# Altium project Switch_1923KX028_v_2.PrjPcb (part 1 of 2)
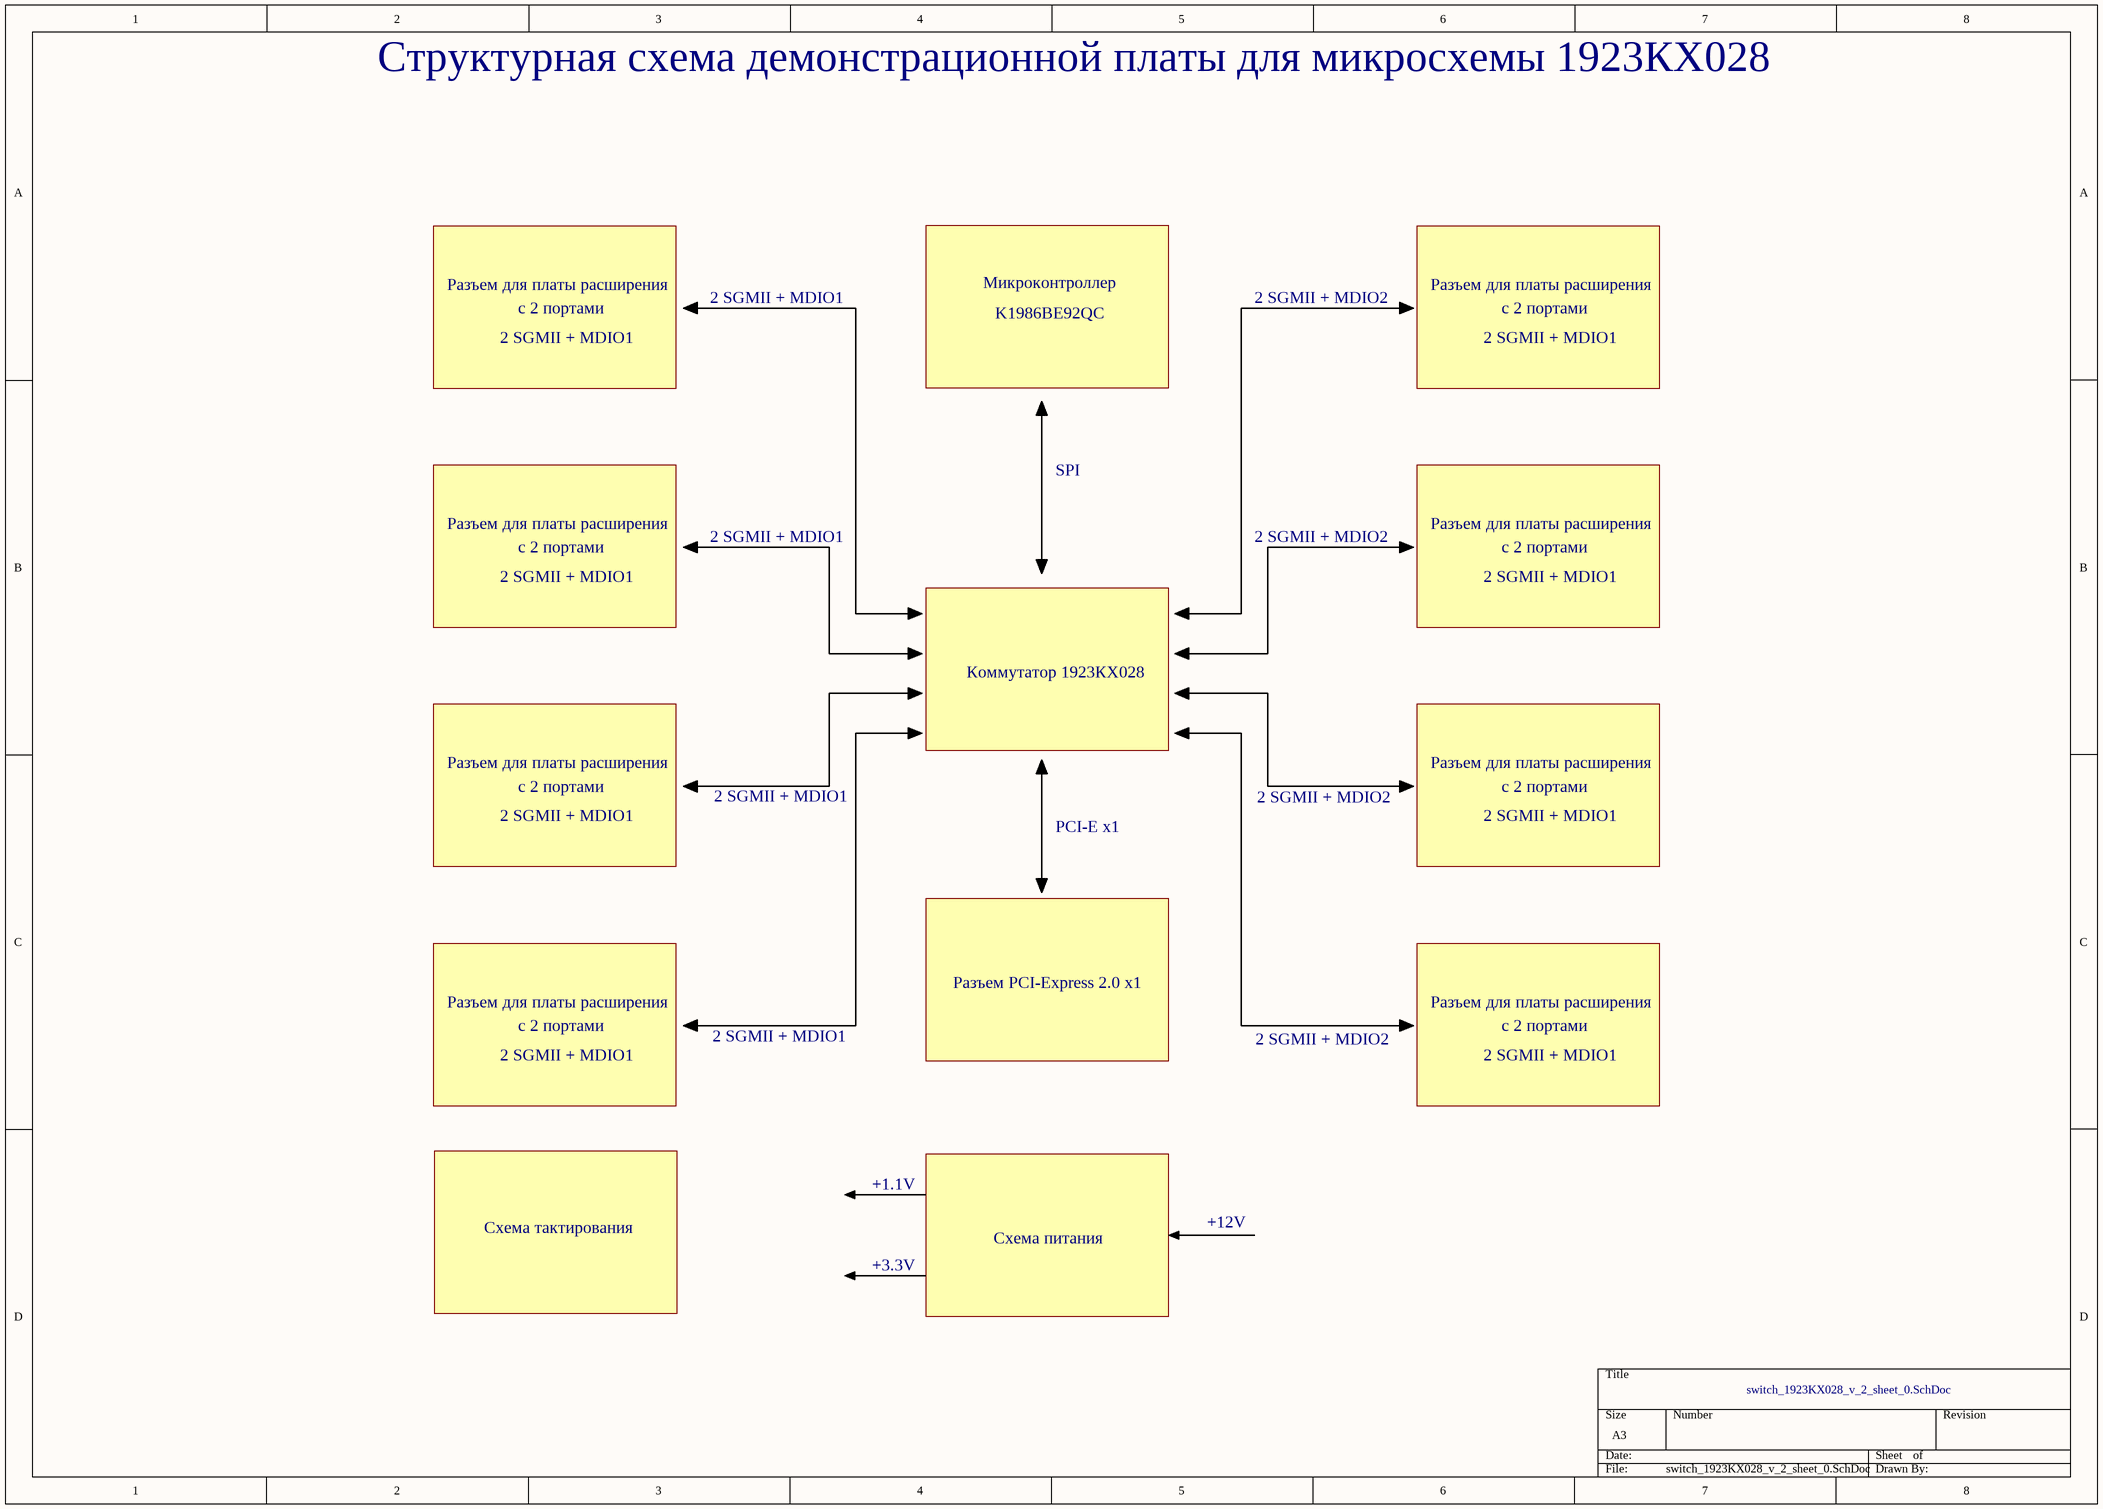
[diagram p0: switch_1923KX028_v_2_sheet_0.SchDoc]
9 sheets, 545 parts. Net scope: global (net labels, ports and power ports of the same name join across sheets).
Board file: pcb_switch_1923KX028_v_2.PcbDoc
Sheets:
  switch_1923KX028_v_2_sheet_0.SchDoc
  switch_1923KX028_v_2_sheet_1.SchDoc
  switch_1923KX028_v_2_sheet_2.SchDoc
  switch_1923KX028_v_2_sheet_3.SchDoc
  switch_1923KX028_v_2_sheet_4.SchDoc
  switch_1923KX028_v_2_sheet_5.SchDoc
  switch_1923KX028_v_2_sheet_6.SchDoc
  switch_1923KX028_v_2_sheet_7.SchDoc
  switch_1923KX028_v_2_sheet_8.SchDoc

## Sheet switch_1923KX028_v_2_sheet_0.SchDoc
size A3; DocumentNumber: 1; SheetNumber: 1; SheetTotal: 10; PageSetup: Record=PageOptions¦CenterHorizontal=True¦CenterVertical=True¦PrintScale=1.04¦XCorrection=1.00¦YCorrection=1.00¦PrintKind=1¦BorderSize=5000000¦LeftOffset=0¦BottomOffset=0¦Orientation=2¦PaperLength=1000¦PaperWidth=1000¦Scale=100¦PaperSource=7¦PrintQuality=-3¦MediaType=1¦DitherType=10¦PrintScaleMode=1¦PaperKind=A3¦PaperIndex=8

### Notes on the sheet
- Структурная схема демонстрационной платы для микросхемы 1923КХ028
- Разъем для платы расширения
- с 2 портами
- 2 SGMII + MDIO1
- Микроконтроллер
- 2 SGMII + MDIO2
- K1986ВЕ92QC
- SPI
- Коммутатор 1923КХ028
- PCI-E x1
- Разъем PCI-Express 2.0 x1
- +1.1V
- Схема тактирования
- Схема питания
- +12V
- +3.3V

## Sheet switch_1923KX028_v_2_sheet_1.SchDoc
size A3; DocumentNumber: 2; SheetNumber: 2; SheetTotal: 10
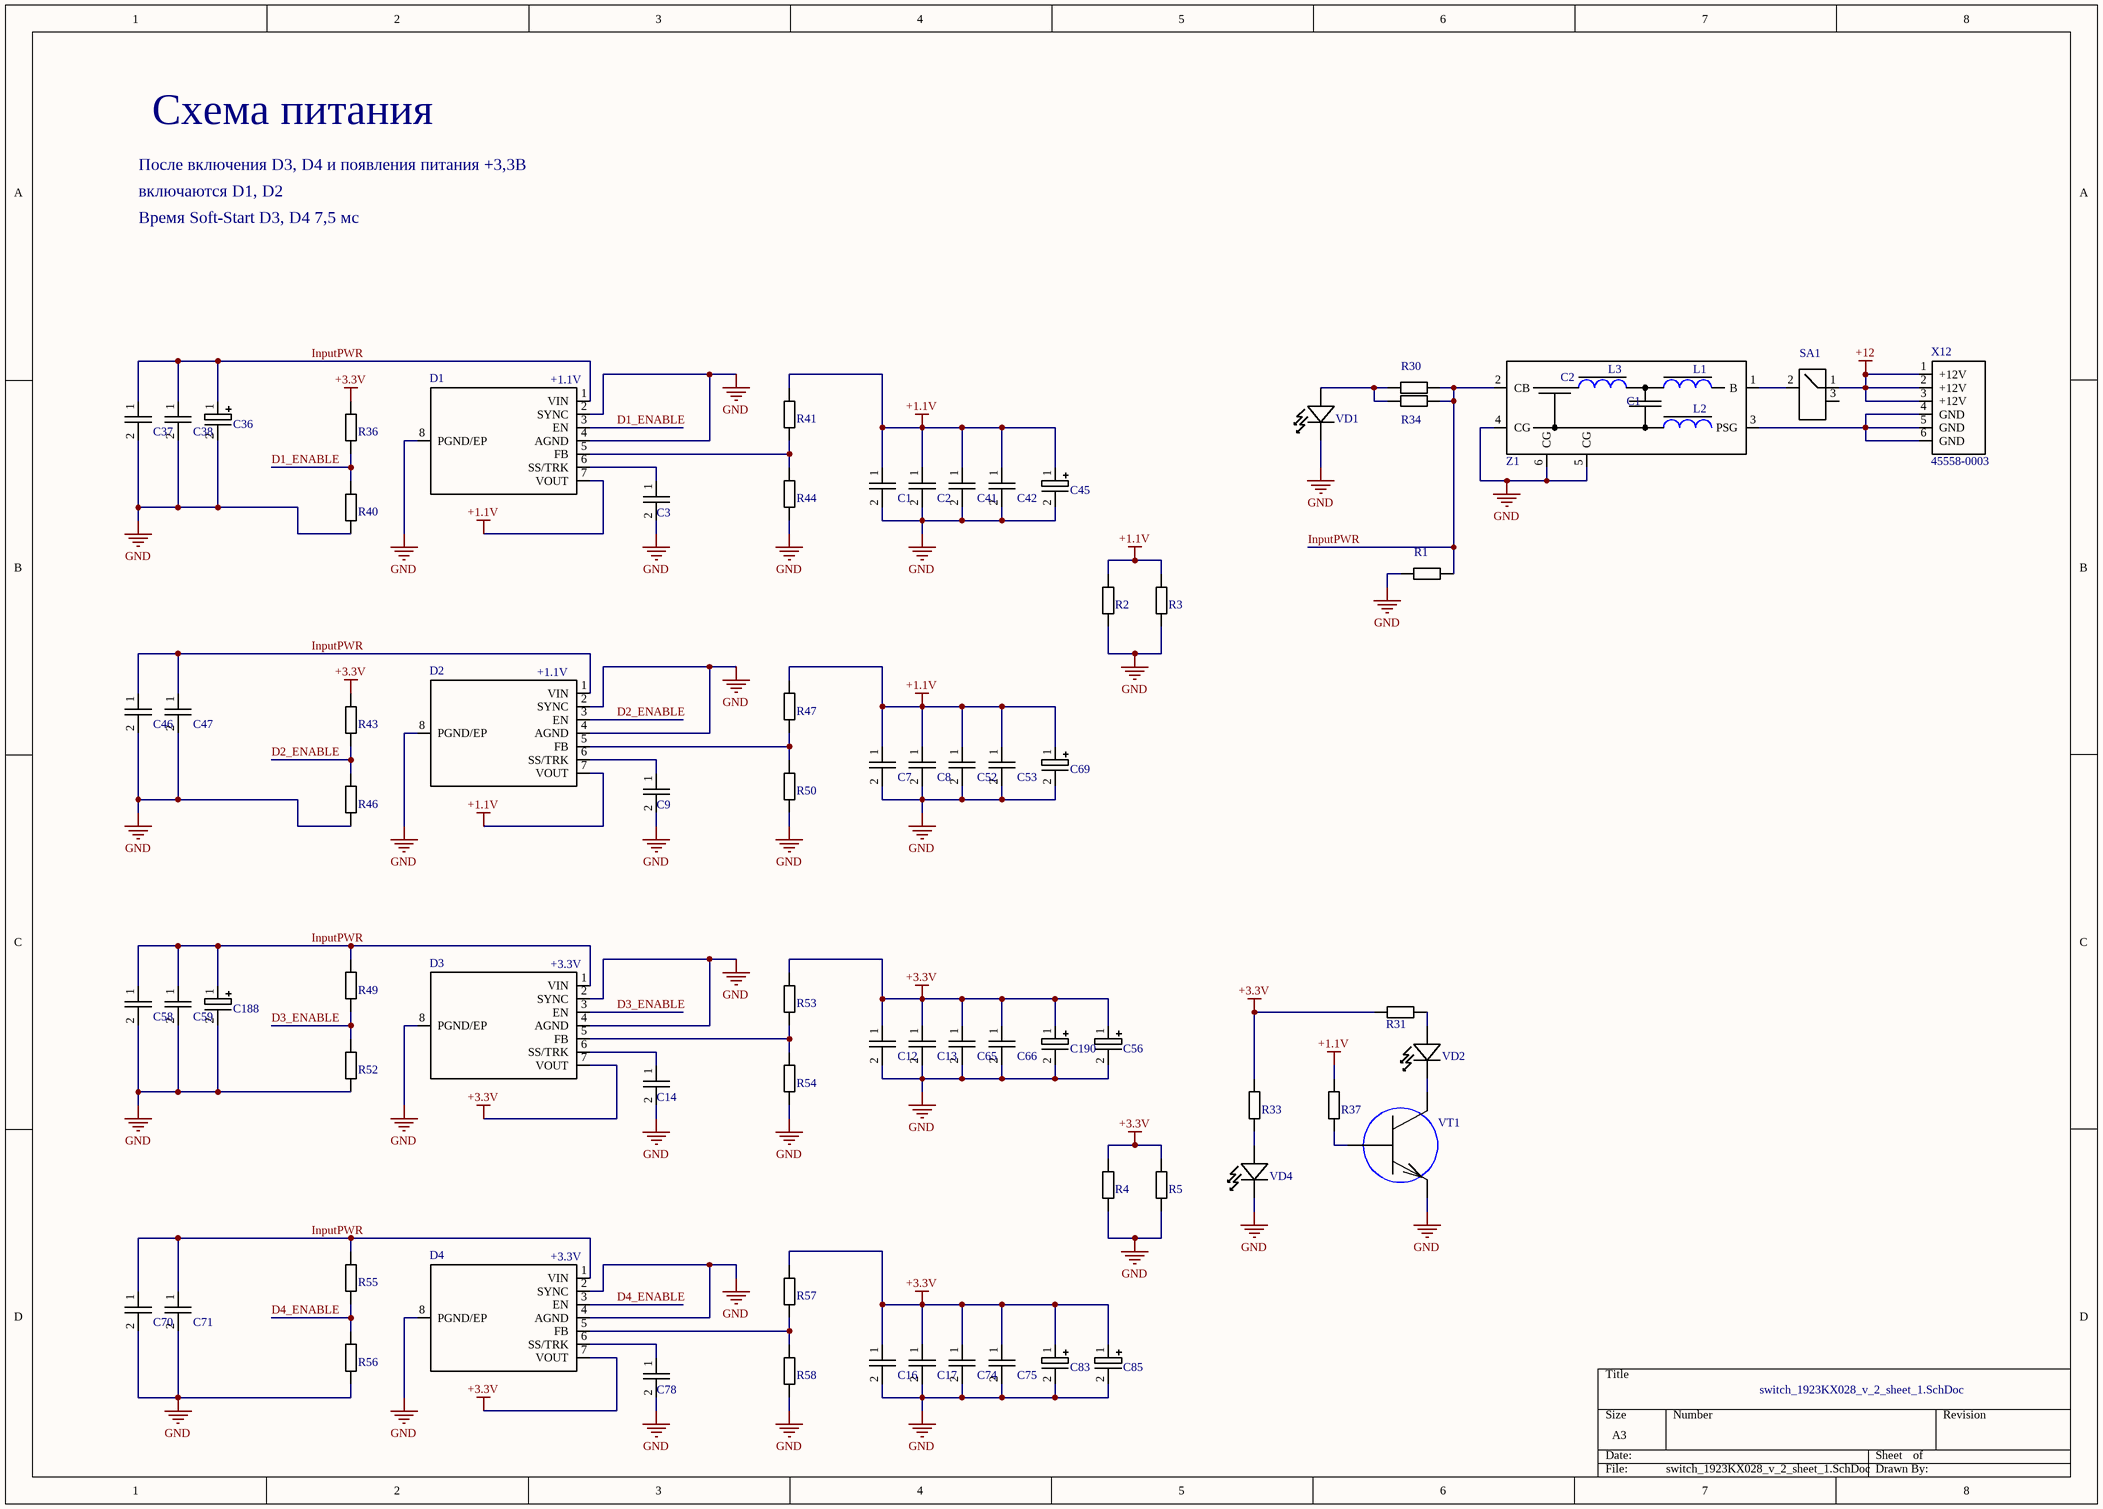
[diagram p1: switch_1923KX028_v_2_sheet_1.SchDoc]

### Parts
C1  100uF, X5R, 6.3В, 1206  [FOOTPRINT_1206]  (value not drawn)
C2  100uF, X5R, 6.3В, 1206  [FOOTPRINT_1206]  (value not drawn)
C3  100nF, 10V, X5R, 0402  [FOOTPRINT_0402]  (value not drawn)
C7  100uF, X5R, 6.3В, 1206  [FOOTPRINT_1206]  (value not drawn)
C8  100uF, X5R, 6.3В, 1206  [FOOTPRINT_1206]  (value not drawn)
C9  100nF, 10V, X5R, 0402  [FOOTPRINT_0402]  (value not drawn)
C12  100uF, X5R, 6.3В, 1206  [FOOTPRINT_1206]  (value not drawn)
C13  100uF, X5R, 6.3В, 1206  [FOOTPRINT_1206]  (value not drawn)
C14  470nF, X7R, 16V, 10%, 0603  [FOOTPRINT_0603]  (value not drawn)
C16  100uF, X5R, 6.3В, 1206  [FOOTPRINT_1206]  (value not drawn)
C17  100uF, X5R, 6.3В, 1206  [FOOTPRINT_1206]  (value not drawn)
C36  470uF, 16V, SMD, 10.3 x 10.3  [FOOTPRINT_SVPE_F12]  (value not drawn)
C37  10 uF, 10%, 25V, X5R, 1206  [FOOTPRINT_1206]  (value not drawn)
C38  10 uF, 10%, 25V, X5R, 1206  [FOOTPRINT_1206]  (value not drawn)
C41  10 uF, 10%, 25V, X5R, 1206  [FOOTPRINT_1206]  (value not drawn)
C42  10 uF, 10%, 25V, X5R, 1206  [FOOTPRINT_1206]  (value not drawn)
C45  470uF, 16V, SMD, 10.3 x 10.3  [FOOTPRINT_SVPE_F12]  (value not drawn)
C46  10 uF, 10%, 25V, X5R, 1206  [FOOTPRINT_1206]  (value not drawn)
C47  10 uF, 10%, 25V, X5R, 1206  [FOOTPRINT_1206]  (value not drawn)
C52  10 uF, 10%, 25V, X5R, 1206  [FOOTPRINT_1206]  (value not drawn)
C53  10 uF, 10%, 25V, X5R, 1206  [FOOTPRINT_1206]  (value not drawn)
C56  470uF, 16V, SMD, 10.3 x 10.3  [FOOTPRINT_SVPE_F12]  (value not drawn)
C58  10 uF, 10%, 25V, X5R, 1206  [FOOTPRINT_1206]  (value not drawn)
C59  10 uF, 10%, 25V, X5R, 1206  [FOOTPRINT_1206]  (value not drawn)
C65  10 uF, 10%, 25V, X5R, 1206  [FOOTPRINT_1206]  (value not drawn)
C66  10 uF, 10%, 25V, X5R, 1206  [FOOTPRINT_1206]  (value not drawn)
C69  470uF, 16V, SMD, 10.3 x 10.3  [FOOTPRINT_SVPE_F12]  (value not drawn)
C70  10 uF, 10%, 25V, X5R, 1206  [FOOTPRINT_1206]  (value not drawn)
C71  10 uF, 10%, 25V, X5R, 1206  [FOOTPRINT_1206]  (value not drawn)
C74  10 uF, 10%, 25V, X5R, 1206  [FOOTPRINT_1206]  (value not drawn)
C75  10 uF, 10%, 25V, X5R, 1206  [FOOTPRINT_1206]  (value not drawn)
C78  470nF, X7R, 16V, 10%, 0603  [FOOTPRINT_0603]  (value not drawn)
C83  470uF, 16V, SMD, 10.3 x 10.3  [FOOTPRINT_SVPE_F12]  (value not drawn)
C85  470uF, 16V, SMD, 10.3 x 10.3  [FOOTPRINT_SVPE_F12]  (value not drawn)
C188  470uF, 16V, SMD, 10.3 x 10.3  [FOOTPRINT_SVPE_F12]  (value not drawn)
C190  470uF, 16V, SMD, 10.3 x 10.3  [FOOTPRINT_SVPE_F12]  (value not drawn)
D1  LMZ22005  [LMZ22005TZ]  (value not drawn)
D2  LMZ22005  [LMZ22005TZ]  (value not drawn)
D3  LMZ22005  [LMZ22005TZ]  (value not drawn)
D4  LMZ22005  [LMZ22005TZ]  (value not drawn)
R1  4.02K 1% 0805  [FOOTPRINT_0805]  (value not drawn)
R2  280 1% 0402  [FOOTPRINT_0402]  (value not drawn)
R3  280 1% 0402  [FOOTPRINT_0402]  (value not drawn)
R4  680, 5%, 0603  [FOOTPRINT_0603]  (value not drawn)
R5  680, 5%, 0603  [FOOTPRINT_0603]  (value not drawn)
R30  4.02K 1% 0805  [FOOTPRINT_0805]  (value not drawn)
R31  49.9, 1%, 0402  [FOOTPRINT_0402]  (value not drawn)
R33  280 1% 0402  [FOOTPRINT_0402]  (value not drawn)
R34  4.02K 1% 0805  [FOOTPRINT_0805]  (value not drawn)
R36  523, 1%, 0603  [FOOTPRINT_0603]  (value not drawn)
R37  33.2K 1% 0603  [FOOTPRINT_0603]  (value not drawn)
R40  470, 1%, 0603  [FOOTPRINT_0603]  (value not drawn)
R41  2K, 1%, 0603  [FOOTPRINT_0603]  (value not drawn)
R43  523, 1%, 0603  [FOOTPRINT_0603]  (value not drawn)
R44  5.23K, 1%, 0603  [FOOTPRINT_0603]  (value not drawn)
R46  470, 1%, 0603  [FOOTPRINT_0603]  (value not drawn)
R47  2K, 1%, 0603  [FOOTPRINT_0603]  (value not drawn)
R49  35.7K, 1%, 0603  [FOOTPRINT_0603]  (value not drawn)
R50  5.23K, 1%, 0603  [FOOTPRINT_0603]  (value not drawn)
R52  5.23K, 1%, 0603  [FOOTPRINT_0603]  (value not drawn)
R53  5.23K, 1%, 0603  [FOOTPRINT_0603]  (value not drawn)
R54  1.65K, 1%, 0603  [FOOTPRINT_0603]  (value not drawn)
R55  35.7K, 1%, 0603  [FOOTPRINT_0603]  (value not drawn)
R56  5.23K, 1%, 0603  [FOOTPRINT_0603]  (value not drawn)
R57  5.23K, 1%, 0603  [FOOTPRINT_0603]  (value not drawn)
R58  1.65K, 1%, 0603  [FOOTPRINT_0603]  (value not drawn)
SA1  R19A-12BBBT-G  [pwr_switch]  (value not drawn)
VD1  KP-2012SYCK  [FOOTPRINT_SMD_LED_2.0x1.25mm]  (value not drawn)
VD2  KP-2012SYCK  [FOOTPRINT_SMD_LED_2.0x1.25mm]  (value not drawn)
VD4  KP-2012SYCK  [FOOTPRINT_SMD_LED_2.0x1.25mm]  (value not drawn)
VT1  BC846B  [FOOTPRINT_SOT-23]  (value not drawn)
X12  45558-0003  [45558-0003]
Z1  BNX016  [BNX016]  (value not drawn)

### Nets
+1.1V: C1.1 C2.1 C7.1 C8.1 C41.1 C42.1 C45.1 C52.1 C53.1 C69.1 D1.7(VOUT) D2.7(VOUT) R2.2 R3.2 R37.1 R41.2 R47.2
+3.3V: C12.1 C13.1 C16.1 C17.1 C56.1 C65.1 C66.1 C74.1 C75.1 C83.1 C85.1 C190.1 D3.7(VOUT) D4.7(VOUT) R4.2 R5.2 R31.2 R33.1 R36.1 R43.1 R53.2 R57.2
+12: SA1.1 X12.1(+12V) X12.2(+12V) X12.3(+12V)
GND: C1.2 C2.2 C3.2 C7.2 C8.2 C9.2 C12.2 C13.2 C14.2 C16.2 C17.2 C36.2 C37.2 C38.2 C41.2 C42.2 C45.2 C46.2 C47.2 C52.2 C53.2 C56.2 C58.2 C59.2 C65.2 C66.2 C69.2 C70.2 C71.2 C74.2 C75.2 C78.2 C83.2 C85.2 C188.2 C190.2 D1.2(SYNC) D1.4(AGND) D1.8(PGND/EP) D2.2(SYNC) D2.4(AGND) D2.8(PGND/EP) D3.2(SYNC) D3.4(AGND) D3.8(PGND/EP) D4.2(SYNC) D4.4(AGND) D4.8(PGND/EP) R1.2 R2.1 R3.1 R4.1 R5.1 R40.2 R44.2 R46.2 R50.2 R52.2 R54.2 R56.2 R58.2 VD1.2(C) VD4.2(C) VT1.2(E) Z1.4(CG) Z1.5(CG) Z1.6(CG)
D1_ENABLE: D1.3(EN) R36.2 R40.1
D2_ENABLE: D2.3(EN) R43.2 R46.1
D3_ENABLE: D3.3(EN) R49.2 R52.1
D4_ENABLE: D4.3(EN) R55.2 R56.1
InputPWR: C36.1 C37.1 C38.1 C46.1 C47.1 C58.1 C59.1 C70.1 C71.1 C188.1 D1.1(VIN) D2.1(VIN) D3.1(VIN) D4.1(VIN) R1.1 R30.1 R34.1 R49.1 R55.1 Z1.2(CB)
NetC3_1: C3.1 D1.6(SS/TRK)
NetC9_1: C9.1 D2.6(SS/TRK)
NetC14_1: C14.1 D3.6(SS/TRK)
NetC78_1: C78.1 D4.6(SS/TRK)
NetD1_5: D1.5(FB) R41.1 R44.1
NetD2_5: D2.5(FB) R47.1 R50.1
NetD3_5: D3.5(FB) R53.1 R54.1
NetD4_5: D4.5(FB) R57.1 R58.1
NetR30_2: R30.2 R34.2 VD1.1(A)
NetR31_1: R31.1 VD2.1(A)
NetR33_2: R33.2 VD4.1(A)
NetR37_2: R37.2 VT1.1(B)
NetSA1_2: SA1.2 Z1.1(B)
NetVD2_2: VD2.2(C) VT1.3(C)
NetX12_4: X12.4(GND) X12.5(GND) X12.6(GND) Z1.3(PSG)

Not connected (* = marked no-connect by the designer): SA1 3

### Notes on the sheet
- После включения D3, D4 и появления питания +3,3В
- Схема питания
- Время Soft-Start D3, D4 7,5 мс
- включаются D1, D2
- (near D1) +1.1V
- (near D2) +1.1V
- (near D3) +3.3V
- (near D4) +3.3V

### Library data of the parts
C1 C2 C7 C8 C12 C13 C16 C17 = Cap_1206: GRM31CR60J107ME39L
C3 C9 = Cap: 0402ZD104KAT2A
C14 C78 = Cap: 0603YC474KAT2A
C36 C45 C56 C69 C83 C85 C188 C190 = Cap_pol_OSCON_16SVPE470M: 16SVPE470M
C37 C38 C41 C42 C46 C47 C52 C53 C58 C59 C65 C66 C70 C71 C74 C75 = Cap_1206: 12063D106KAT2A
R1 R30 R34 = Res_0805: CR0805-FX-4021ELF
R2 R3 R33 = Res: CR0402-FX-2800GLF
R4 R5 = Res: CR0603-JW-681ELF
R31 = Res: CR0603-FX-49R9ELF
R36 R43 = Res: CR0603-FX-5230ELF
R37 = Res: CR0603-FX-3322ELF
R40 R46 = Res: CR0603-FX-4700ELF
R41 R47 = Res: CR0603-FX-2001ELF
R44 R50 R52 R53 R56 R57 = Res: CR0603-FX-5231ELF
R49 R55 = Res: CR0603-FX-3572ELF
R54 R58 = Res: CR0603-FX-1651ELF
SA1 = pwr_switch: 768, Переключатель, 2 конт., 250В/6.0А
VD1 VD2 VD4 = Vd_led: kingbright 2.0 x 1.25mm SMD CHIP LED LAMP
VT1 = VT

## Sheet switch_1923KX028_v_2_sheet_2.SchDoc
size A3; DocumentNumber: 3; SheetNumber: 3; SheetTotal: 10; PageSetup: Record=PageOptions¦CenterHorizontal=True¦CenterVertical=True¦PrintScale=0.73¦XCorrection=1.00¦YCorrection=1.00¦PrintKind=1¦BorderSize=5000000¦LeftOffset=0¦BottomOffset=0¦Orientation=2¦PaperLength=1000¦PaperWidth=1000¦Scale=100¦PaperSource=7¦PrintQuality=600¦MediaType=1¦DitherType=10¦PrintScaleMode=1¦PaperKind=A4¦PaperIndex=9
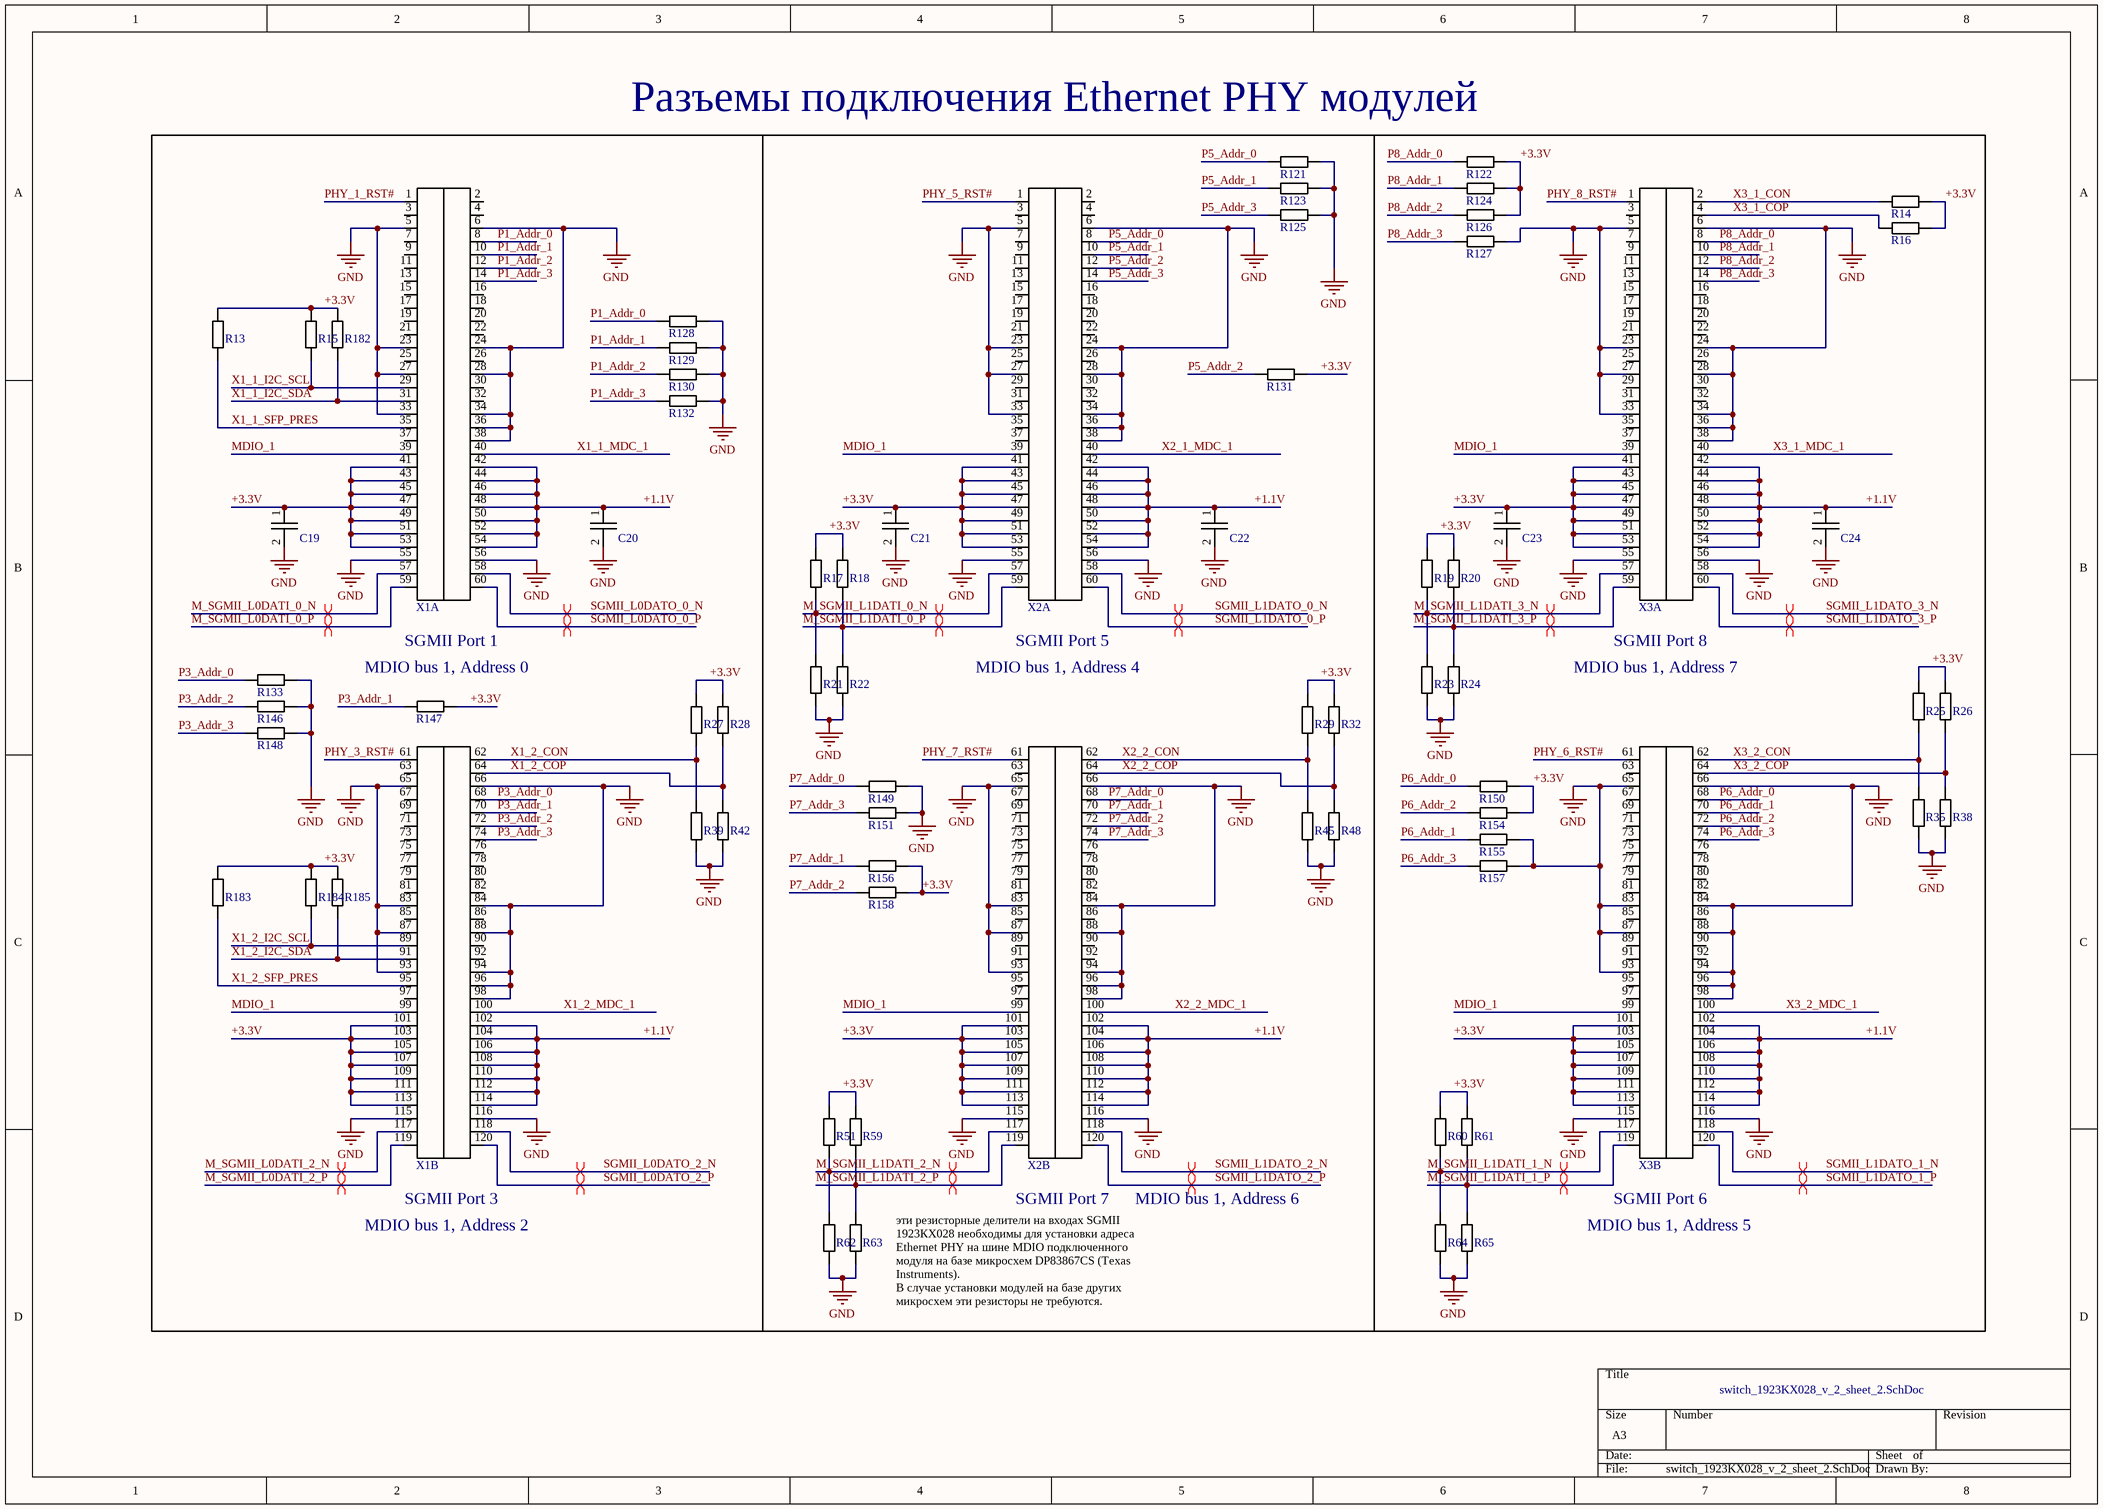
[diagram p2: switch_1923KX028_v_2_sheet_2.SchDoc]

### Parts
C19  100uF, X5R, 6.3В, 1206  [FOOTPRINT_1206]  (value not drawn)
C20  100uF, X5R, 6.3В, 1206  [FOOTPRINT_1206]  (value not drawn)
C21  100uF, X5R, 6.3В, 1206  [FOOTPRINT_1206]  (value not drawn)
C22  100uF, X5R, 6.3В, 1206  [FOOTPRINT_1206]  (value not drawn)
C23  100uF, X5R, 6.3В, 1206  [FOOTPRINT_1206]  (value not drawn)
C24  100uF, X5R, 6.3В, 1206  [FOOTPRINT_1206]  (value not drawn)
R13  11K, 1%, 0402  [FOOTPRINT_0402]  (value not drawn)
R14  2.49K, 1%, 0402  [FOOTPRINT_0402]  (value not drawn)
R15  11K, 1%, 0402  [FOOTPRINT_0402]  (value not drawn)
R16  2.49K, 1%, 0402  [FOOTPRINT_0402]  (value not drawn)
R17  11K, 1%, 0402  [FOOTPRINT_0402]  (value not drawn)
R18  11K, 1%, 0402  [FOOTPRINT_0402]  (value not drawn)
R19  11K, 1%, 0402  [FOOTPRINT_0402]  (value not drawn)
R20  11K, 1%, 0402  [FOOTPRINT_0402]  (value not drawn)
R21  2.49K, 1%, 0402  [FOOTPRINT_0402]  (value not drawn)
R22  2.49K, 1%, 0402  [FOOTPRINT_0402]  (value not drawn)
R23  2.49K, 1%, 0402  [FOOTPRINT_0402]  (value not drawn)
R24  2.49K, 1%, 0402  [FOOTPRINT_0402]  (value not drawn)
R25  11K, 1%, 0402  [FOOTPRINT_0402]  (value not drawn)
R26  11K, 1%, 0402  [FOOTPRINT_0402]  (value not drawn)
R27  6.04K, 1%, 0402  [FOOTPRINT_0402]  (value not drawn)
R28  6.04K, 1%, 0402  [FOOTPRINT_0402]  (value not drawn)
R29  6.04K, 1%, 0402  [FOOTPRINT_0402]  (value not drawn)
R32  6.04K, 1%, 0402  [FOOTPRINT_0402]  (value not drawn)
R35  2.49K, 1%, 0402  [FOOTPRINT_0402]  (value not drawn)
R38  2.49K, 1%, 0402  [FOOTPRINT_0402]  (value not drawn)
R39  2.49K, 1%, 0402  [FOOTPRINT_0402]  (value not drawn)
R42  2.49K, 1%, 0402  [FOOTPRINT_0402]  (value not drawn)
R45  2.49K, 1%, 0402  [FOOTPRINT_0402]  (value not drawn)
R48  2.49K, 1%, 0402  [FOOTPRINT_0402]  (value not drawn)
R51  11K, 1%, 0402  [FOOTPRINT_0402]  (value not drawn)
R59  11K, 1%, 0402  [FOOTPRINT_0402]  (value not drawn)
R60  11K, 1%, 0402  [FOOTPRINT_0402]  (value not drawn)
R61  11K, 1%, 0402  [FOOTPRINT_0402]  (value not drawn)
R62  2.49K, 1%, 0402  [FOOTPRINT_0402]  (value not drawn)
R63  2.49K, 1%, 0402  [FOOTPRINT_0402]  (value not drawn)
R64  2.49K, 1%, 0402  [FOOTPRINT_0402]  (value not drawn)
R65  2.49K, 1%, 0402  [FOOTPRINT_0402]  (value not drawn)
R121  2.49K, 1%, 0402  [FOOTPRINT_0402]  (value not drawn)
R122  2.49K, 1%, 0402  [FOOTPRINT_0402]  (value not drawn)
R123  2.49K, 1%, 0402  [FOOTPRINT_0402]  (value not drawn)
R124  2.49K, 1%, 0402  [FOOTPRINT_0402]  (value not drawn)
R125  2.49K, 1%, 0402  [FOOTPRINT_0402]  (value not drawn)
R126  2.49K, 1%, 0402  [FOOTPRINT_0402]  (value not drawn)
R127  2.49K, 1%, 0402  [FOOTPRINT_0402]  (value not drawn)
R128  2.49K, 1%, 0402  [FOOTPRINT_0402]  (value not drawn)
R129  2.49K, 1%, 0402  [FOOTPRINT_0402]  (value not drawn)
R130  2.49K, 1%, 0402  [FOOTPRINT_0402]  (value not drawn)
R131  2.49K, 1%, 0402  [FOOTPRINT_0402]  (value not drawn)
R132  2.49K, 1%, 0402  [FOOTPRINT_0402]  (value not drawn)
R133  2.49K, 1%, 0402  [FOOTPRINT_0402]  (value not drawn)
R146  2.49K, 1%, 0402  [FOOTPRINT_0402]  (value not drawn)
R147  2.49K, 1%, 0402  [FOOTPRINT_0402]  (value not drawn)
R148  2.49K, 1%, 0402  [FOOTPRINT_0402]  (value not drawn)
R149  2.49K, 1%, 0402  [FOOTPRINT_0402]  (value not drawn)
R150  2.49K, 1%, 0402  [FOOTPRINT_0402]  (value not drawn)
R151  2.49K, 1%, 0402  [FOOTPRINT_0402]  (value not drawn)
R154  2.49K, 1%, 0402  [FOOTPRINT_0402]  (value not drawn)
R155  2.49K, 1%, 0402  [FOOTPRINT_0402]  (value not drawn)
R156  2.49K, 1%, 0402  [FOOTPRINT_0402]  (value not drawn)
R157  2.49K, 1%, 0402  [FOOTPRINT_0402]  (value not drawn)
R158  2.49K, 1%, 0402  [FOOTPRINT_0402]  (value not drawn)
R182  11K, 1%, 0402  [FOOTPRINT_0402]  (value not drawn)
R183  11K, 1%, 0402  [FOOTPRINT_0402]  (value not drawn)
R184  11K, 1%, 0402  [FOOTPRINT_0402]  (value not drawn)
R185  11K, 1%, 0402  [FOOTPRINT_0402]  (value not drawn)
X1  qsh-60-01-f-d-a  [QSH-60-01-F-D-A]  (value not drawn)  (parts A,B of 2)
X2  qsh-60-01-f-d-a  [QSH-60-01-F-D-A]  (value not drawn)  (parts A,B of 2)
X3  qsh-60-01-f-d-a  [QSH-60-01-F-D-A]  (value not drawn)  (parts A,B of 2)

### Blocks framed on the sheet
Разъемы подключения Ethernet PHY модулей: C21 C22 R17 R18 R21 R22 R29 R32 R45 R48 R51 R59 R62 R63 R121 R123 R125 R131 R149 R151 R156 R158 X2

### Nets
+1.1V: C20.1 C22.1 C24.1 X1.42 X1.44 X1.46 X1.48 X1.50 X1.52 X1.54 X1.102 X1.104 X1.106 X1.108 X1.110 X1.112 X1.114 X2.42 X2.44 X2.46 X2.48 X2.50 X2.52 X2.54 X2.102 X2.104 X2.106 X2.108 X2.110 X2.112 X2.114 X3.42 X3.44 X3.46 X3.48 X3.50 X3.52 X3.54 X3.102 X3.104 X3.106 X3.108 X3.110 X3.112 X3.114
+3.3V: C19.1 C21.1 C23.1 R13.1 R14.1 R15.1 R16.1 R17.1 R18.1 R19.1 R20.1 R25.1 R26.1 R27.1 R28.1 R29.1 R32.1 R51.1 R59.1 R60.1 R61.1 R122.2 R124.2 R126.2 R131.2 R147.2 R150.2 R154.2 R156.2 R158.2 R182.1 R183.1 R184.1 R185.1 X1.41 X1.43 X1.45 X1.47 X1.49 X1.51 X1.53 X1.101 X1.103 X1.105 X1.107 X1.109 X1.111 X1.113 X2.41 X2.43 X2.45 X2.47 X2.49 X2.51 X2.53 X2.101 X2.103 X2.105 X2.107 X2.109 X2.111 X2.113 X3.41 X3.43 X3.45 X3.47 X3.49 X3.51 X3.53 X3.101 X3.103 X3.105 X3.107 X3.109 X3.111 X3.113
GND: C19.2 C20.2 C21.2 C22.2 C23.2 C24.2 R21.2 R22.2 R23.2 R24.2 R35.2 R38.2 R39.2 R42.2 R45.2 R48.2 R62.2 R63.2 R64.2 R65.2 R121.2 R123.2 R125.2 R127.2 R128.2 R129.2 R130.2 R132.2 R133.2 R146.2 R148.2 R149.2 R151.2 R155.2 R157.2 X1.5 X1.6 X1.23 X1.24 X1.27 X1.28 X1.33 X1.34 X1.36 X1.38 X1.55 X1.56 X1.65 X1.66 X1.83 X1.84 X1.87 X1.88 X1.93 X1.94 X1.96 X1.98 X1.115 X1.116 X1.121 X1.122 X1.123 X1.124 X1.125 X1.126 X1.127 X1.128 X2.5 X2.6 X2.23 X2.24 X2.27 X2.28 X2.33 X2.34 X2.36 X2.38 X2.55 X2.56 X2.65 X2.66 X2.83 X2.84 X2.87 X2.88 X2.93 X2.94 X2.96 X2.98 X2.115 X2.116 X2.121 X2.122 X2.123 X2.124 X2.125 X2.126 X2.127 X2.128 X3.5 X3.6 X3.23 X3.24 X3.27 X3.28 X3.33 X3.34 X3.36 X3.38 X3.55 X3.56 X3.65 X3.66 X3.83 X3.84 X3.87 X3.88 X3.93 X3.94 X3.96 X3.98 X3.115 X3.116 X3.121 X3.122 X3.123 X3.124 X3.125 X3.126 X3.127 X3.128
M_SGMII_L0DATI_0_N: X1.57
M_SGMII_L0DATI_0_P: X1.59
M_SGMII_L0DATI_2_N: X1.117
M_SGMII_L0DATI_2_P: X1.119
M_SGMII_L1DATI_0_N: R17.2 R21.1 X2.57
M_SGMII_L1DATI_0_P: R18.2 R22.1 X2.59
M_SGMII_L1DATI_1_N: R60.2 R64.1 X3.117
M_SGMII_L1DATI_1_P: R61.2 R65.1 X3.119
M_SGMII_L1DATI_2_N: R51.2 R62.1 X2.117
M_SGMII_L1DATI_2_P: R59.2 R63.1 X2.119
M_SGMII_L1DATI_3_N: R19.2 R23.1 X3.57
M_SGMII_L1DATI_3_P: R20.2 R24.1 X3.59
MDIO_1: X1.39 X1.99 X2.39 X2.99 X3.39 X3.99
P1_Addr_0: R128.1 X1.8
P1_Addr_1: R129.1 X1.10
P1_Addr_2: R130.1 X1.12
P1_Addr_3: R132.1 X1.14
P3_Addr_0: R133.1 X1.68
P3_Addr_1: R147.1 X1.70
P3_Addr_2: R146.1 X1.72
P3_Addr_3: R148.1 X1.74
P5_Addr_0: R121.1 X2.8
P5_Addr_1: R123.1 X2.10
P5_Addr_2: R131.1 X2.12
P5_Addr_3: R125.1 X2.14
P6_Addr_0: R150.1 X3.68
P6_Addr_1: R155.1 X3.70
P6_Addr_2: R154.1 X3.72
P6_Addr_3: R157.1 X3.74
P7_Addr_0: R149.1 X2.68
P7_Addr_1: R156.1 X2.70
P7_Addr_2: R158.1 X2.72
P7_Addr_3: R151.1 X2.74
P8_Addr_0: R122.1 X3.8
P8_Addr_1: R124.1 X3.10
P8_Addr_2: R126.1 X3.12
P8_Addr_3: R127.1 X3.14
PHY_1_RST#: X1.1
PHY_3_RST#: X1.61
PHY_5_RST#: X2.1
PHY_6_RST#: X3.61
PHY_7_RST#: X2.61
PHY_8_RST#: X3.1
SGMII_L0DATO_0_N: X1.58
SGMII_L0DATO_0_P: X1.60
SGMII_L0DATO_2_N: X1.118
SGMII_L0DATO_2_P: X1.120
SGMII_L1DATO_0_N: X2.58
SGMII_L1DATO_0_P: X2.60
SGMII_L1DATO_1_N: X3.118
SGMII_L1DATO_1_P: X3.120
SGMII_L1DATO_2_N: X2.118
SGMII_L1DATO_2_P: X2.120
SGMII_L1DATO_3_N: X3.58
SGMII_L1DATO_3_P: X3.60
X1_1_I2C_SCL: R15.2 X1.29
X1_1_I2C_SDA: R182.2 X1.31
X1_1_MDC_1: X1.40
X1_1_SFP_PRES: R13.2 X1.35
X1_2_CON: R27.2 R39.1 X1.62
X1_2_COP: R28.2 R42.1 X1.64
X1_2_I2C_SCL: R184.2 X1.89
X1_2_I2C_SDA: R185.2 X1.91
X1_2_MDC_1: X1.100
X1_2_SFP_PRES: R183.2 X1.95
X2_1_MDC_1: X2.40
X2_2_CON: R29.2 R45.1 X2.62
X2_2_COP: R32.2 R48.1 X2.64
X2_2_MDC_1: X2.100
X3_1_CON: R14.2 X3.2
X3_1_COP: R16.2 X3.4
X3_1_MDC_1: X3.40
X3_2_CON: R25.2 R35.1 X3.62
X3_2_COP: R26.2 R38.1 X3.64
X3_2_MDC_1: X3.100

Not connected (* = marked no-connect by the designer): X1 2 3 4 7 9 11 13 15 16 17 18 19 20 21 22 25 26 30 32 37 63 67 69 71 73 75 76 77 78 79 80 81 82 85 86 90 92 97; X2 2 3 4 7 9 11 13 15 16 17 18 19 20 21 22 25 26 29 30 31 32 35 37 63 67 69 71 73 75 76 77 78 79 80 81 82 85 86 89 90 91 92 95 97; X3 3 7 9 11 13 15 16 17 18 19 20 21 22 25 26 29 30 31 32 35 37 63 67 69 71 73 75 76 77 78 79 80 81 82 85 86 89 90 91 92 95 97

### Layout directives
differential pair: M_SGMII_L0DATI_0_N, M_SGMII_L0DATI_0_P, M_SGMII_L0DATI_2_N, M_SGMII_L0DATI_2_P, M_SGMII_L1DATI_0_N, M_SGMII_L1DATI_0_P, M_SGMII_L1DATI_1_N, M_SGMII_L1DATI_1_P, M_SGMII_L1DATI_2_N, M_SGMII_L1DATI_2_P, M_SGMII_L1DATI_3_N, M_SGMII_L1DATI_3_P, SGMII_L0DATO_0_N, SGMII_L0DATO_0_P, SGMII_L0DATO_2_N, SGMII_L0DATO_2_P, SGMII_L1DATO_0_N, SGMII_L1DATO_0_P, SGMII_L1DATO_1_N, SGMII_L1DATO_1_P, SGMII_L1DATO_2_N, SGMII_L1DATO_2_P, SGMII_L1DATO_3_N, SGMII_L1DATO_3_P

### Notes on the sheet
- SGMII Port 1
- (near X2) SGMII Port 5
- (near X3) SGMII Port 8
- (near R147) MDIO bus 1, Address 0
- MDIO bus 1, Address 4
- MDIO bus 1, Address 7
- (near X1) SGMII Port 3
- (near X2) SGMII Port 7
- MDIO bus 1, Address 6
- (near X3) SGMII Port 6
- MDIO bus 1, Address 2
- MDIO bus 1, Address 5
- (near R63) эти резисторные делители на входах SGMII 1923КХ028 необходимы для установки адреса Ethernet PHY на шине MDIO подключенного модуля на базе микросхем DP83867CS (Texas Instruments).
  В случае установки модулей на базе других микросхем эти резисторы не требуются.

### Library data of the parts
C19-C24 = Cap_1206: GRM31CR60J107ME39L
R13 R15 R182-R185 = Res: CR0402-FX-1102GLF
R14 R16 R21-R24 R35 R38 R39 R42 R45 R48 R62-R65 R121-R133 R146-R151 R154-R158 = Res_0402: CR0402-FX-2491GLF
R17-R20 R25 R26 R51 R59-R61 = Res_0402: CR0402-FX-1102GLF
R27-R29 R32 = Res_0402: CR0402-FX-6041GLF
X1-X3 = qsh-60-01-f-d-a: Samtec, high-speed socket, pitch 0.5 mm, 120 pins

## Sheet switch_1923KX028_v_2_sheet_3.SchDoc
size A3
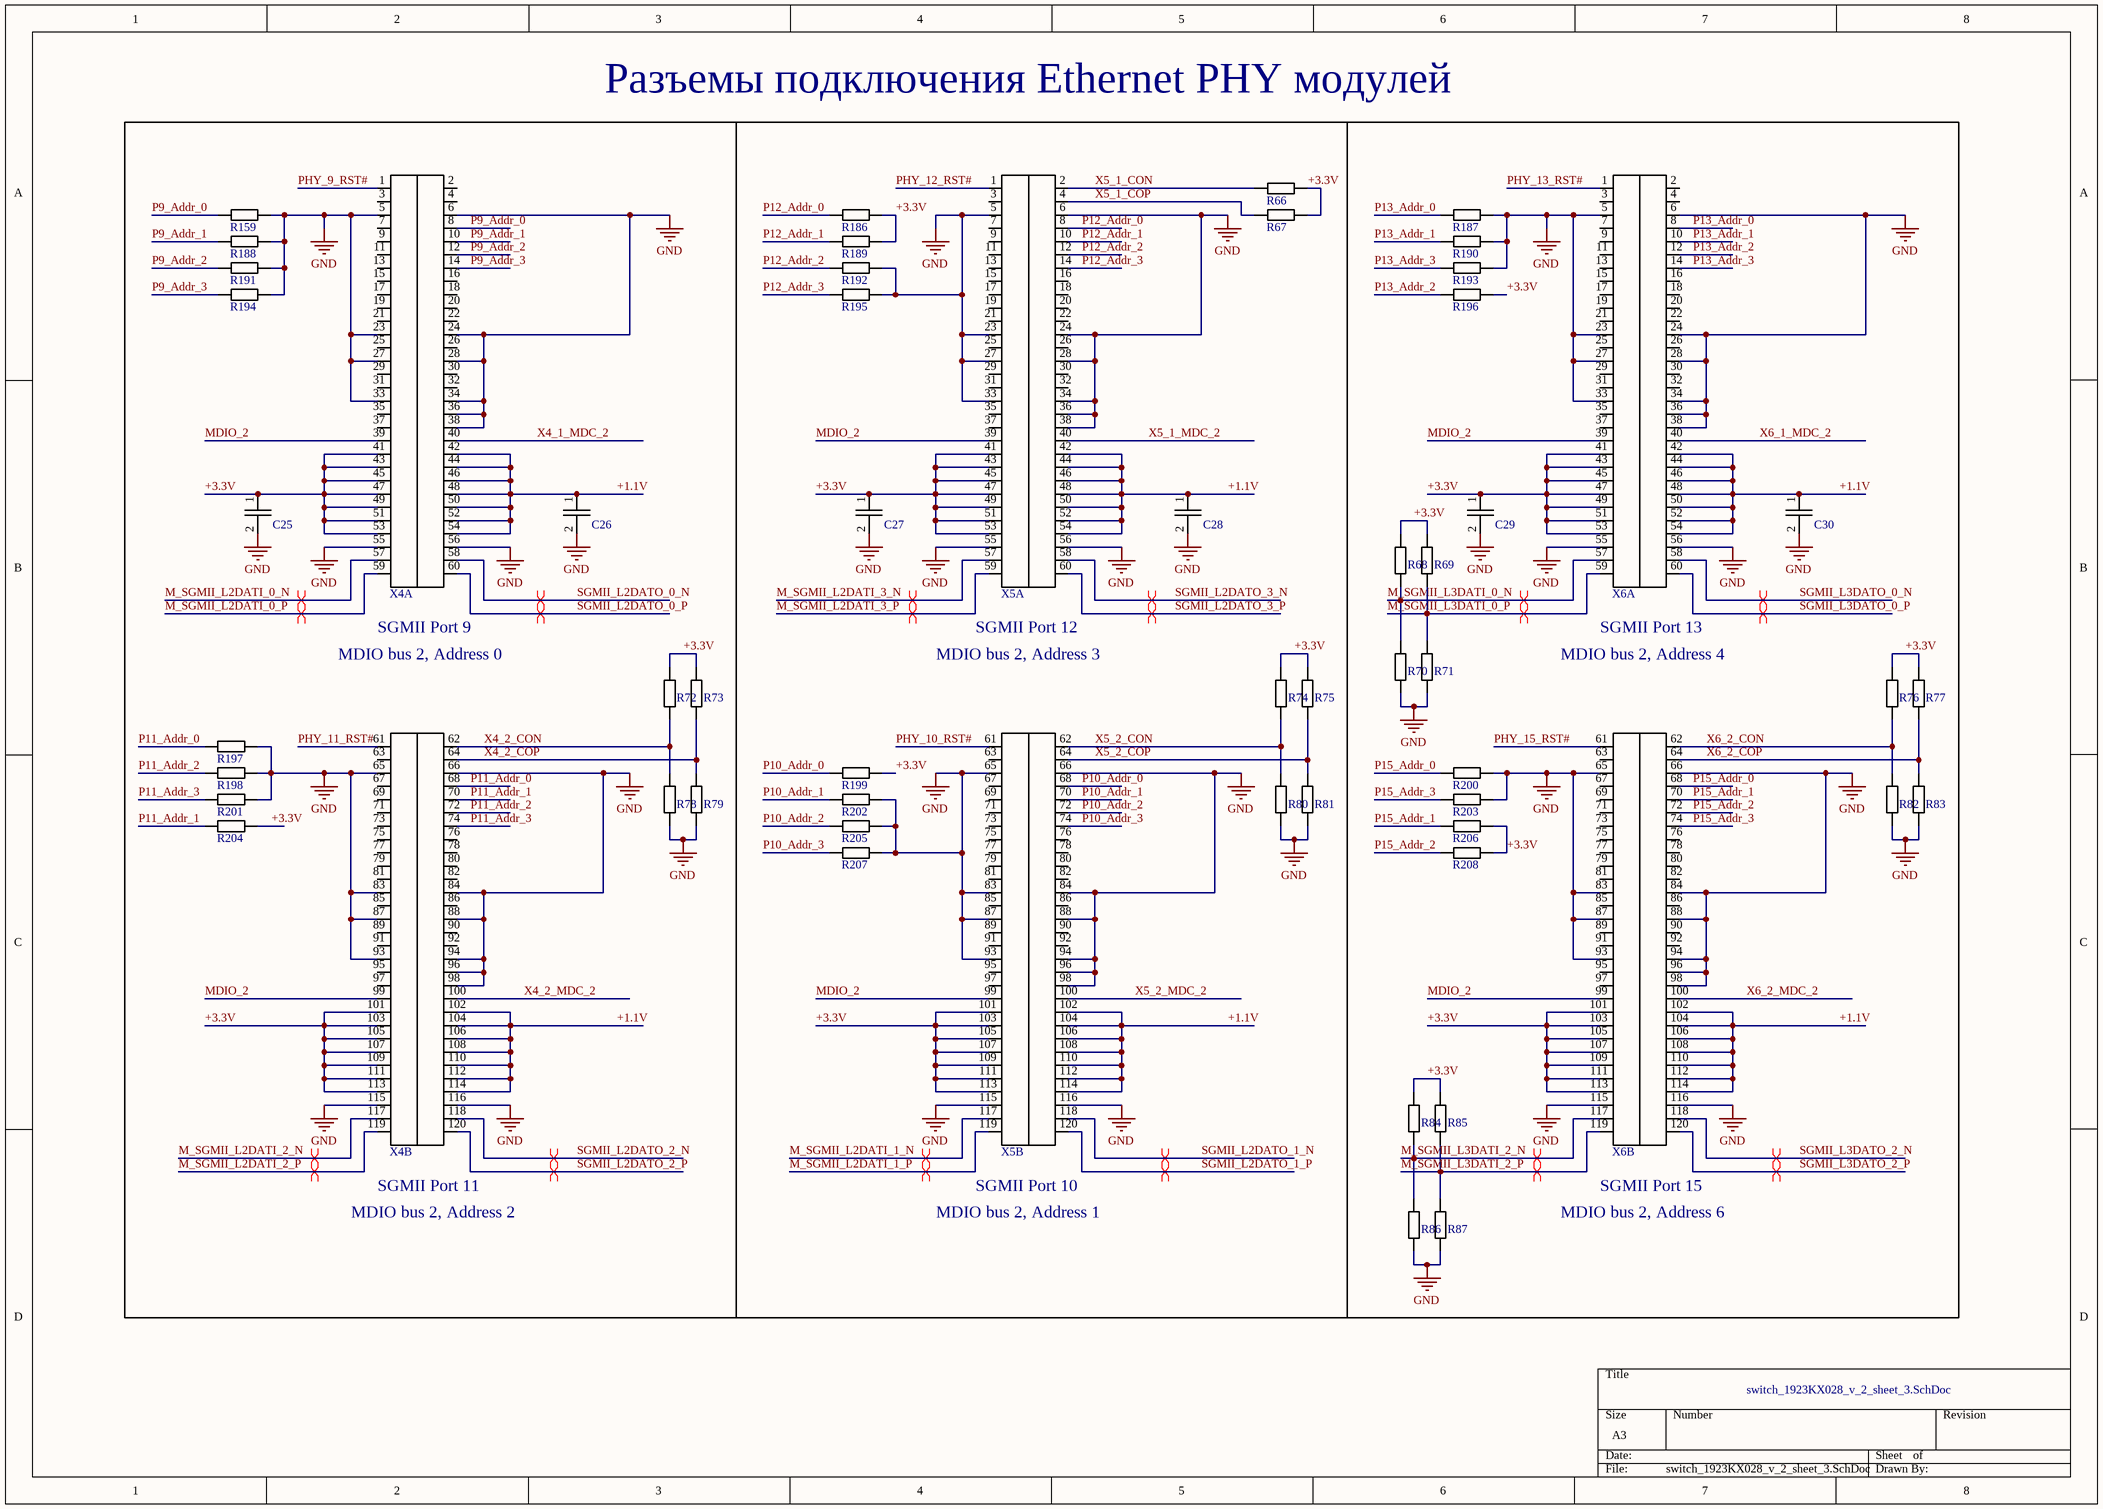
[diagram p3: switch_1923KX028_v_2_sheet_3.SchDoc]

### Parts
C25  100uF, X5R, 6.3В, 1206  [FOOTPRINT_1206]  (value not drawn)
C26  100uF, X5R, 6.3В, 1206  [FOOTPRINT_1206]  (value not drawn)
C27  100uF, X5R, 6.3В, 1206  [FOOTPRINT_1206]  (value not drawn)
C28  100uF, X5R, 6.3В, 1206  [FOOTPRINT_1206]  (value not drawn)
C29  100uF, X5R, 6.3В, 1206  [FOOTPRINT_1206]  (value not drawn)
C30  100uF, X5R, 6.3В, 1206  [FOOTPRINT_1206]  (value not drawn)
R66  2.49K, 1%, 0402  [FOOTPRINT_0402]  (value not drawn)
R67  2.49K, 1%, 0402  [FOOTPRINT_0402]  (value not drawn)
R68  11K, 1%, 0402  [FOOTPRINT_0402]  (value not drawn)
R69  11K, 1%, 0402  [FOOTPRINT_0402]  (value not drawn)
R70  2.49K, 1%, 0402  [FOOTPRINT_0402]  (value not drawn)
R71  2.49K, 1%, 0402  [FOOTPRINT_0402]  (value not drawn)
R72  6.04K, 1%, 0402  [FOOTPRINT_0402]  (value not drawn)
R73  6.04K, 1%, 0402  [FOOTPRINT_0402]  (value not drawn)
R74  11K, 1%, 0402  [FOOTPRINT_0402]  (value not drawn)
R75  11K, 1%, 0402  [FOOTPRINT_0402]  (value not drawn)
R76  6.04K, 1%, 0402  [FOOTPRINT_0402]  (value not drawn)
R77  6.04K, 1%, 0402  [FOOTPRINT_0402]  (value not drawn)
R78  2.49K, 1%, 0402  [FOOTPRINT_0402]  (value not drawn)
R79  2.49K, 1%, 0402  [FOOTPRINT_0402]  (value not drawn)
R80  2.49K, 1%, 0402  [FOOTPRINT_0402]  (value not drawn)
R81  2.49K, 1%, 0402  [FOOTPRINT_0402]  (value not drawn)
R82  2.49K, 1%, 0402  [FOOTPRINT_0402]  (value not drawn)
R83  2.49K, 1%, 0402  [FOOTPRINT_0402]  (value not drawn)
R84  11K, 1%, 0402  [FOOTPRINT_0402]  (value not drawn)
R85  11K, 1%, 0402  [FOOTPRINT_0402]  (value not drawn)
R86  2.49K, 1%, 0402  [FOOTPRINT_0402]  (value not drawn)
R87  2.49K, 1%, 0402  [FOOTPRINT_0402]  (value not drawn)
R159  2.49K, 1%, 0402  [FOOTPRINT_0402]  (value not drawn)
R186  2.49K, 1%, 0402  [FOOTPRINT_0402]  (value not drawn)
R187  2.49K, 1%, 0402  [FOOTPRINT_0402]  (value not drawn)
R188  2.49K, 1%, 0402  [FOOTPRINT_0402]  (value not drawn)
R189  2.49K, 1%, 0402  [FOOTPRINT_0402]  (value not drawn)
R190  2.49K, 1%, 0402  [FOOTPRINT_0402]  (value not drawn)
R191  2.49K, 1%, 0402  [FOOTPRINT_0402]  (value not drawn)
R192  2.49K, 1%, 0402  [FOOTPRINT_0402]  (value not drawn)
R193  2.49K, 1%, 0402  [FOOTPRINT_0402]  (value not drawn)
R194  2.49K, 1%, 0402  [FOOTPRINT_0402]  (value not drawn)
R195  2.49K, 1%, 0402  [FOOTPRINT_0402]  (value not drawn)
R196  2.49K, 1%, 0402  [FOOTPRINT_0402]  (value not drawn)
R197  2.49K, 1%, 0402  [FOOTPRINT_0402]  (value not drawn)
R198  2.49K, 1%, 0402  [FOOTPRINT_0402]  (value not drawn)
R199  2.49K, 1%, 0402  [FOOTPRINT_0402]  (value not drawn)
R200  2.49K, 1%, 0402  [FOOTPRINT_0402]  (value not drawn)
R201  2.49K, 1%, 0402  [FOOTPRINT_0402]  (value not drawn)
R202  2.49K, 1%, 0402  [FOOTPRINT_0402]  (value not drawn)
R203  2.49K, 1%, 0402  [FOOTPRINT_0402]  (value not drawn)
R204  2.49K, 1%, 0402  [FOOTPRINT_0402]  (value not drawn)
R205  2.49K, 1%, 0402  [FOOTPRINT_0402]  (value not drawn)
R206  2.49K, 1%, 0402  [FOOTPRINT_0402]  (value not drawn)
R207  2.49K, 1%, 0402  [FOOTPRINT_0402]  (value not drawn)
R208  2.49K, 1%, 0402  [FOOTPRINT_0402]  (value not drawn)
X4  qsh-60-01-f-d-a  [QSH-60-01-F-D-A]  (value not drawn)  (parts A,B of 2)
X5  qsh-60-01-f-d-a  [QSH-60-01-F-D-A]  (value not drawn)  (parts A,B of 2)
X6  qsh-60-01-f-d-a  [QSH-60-01-F-D-A]  (value not drawn)  (parts A,B of 2)

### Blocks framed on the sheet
Разъемы подключения Ethernet PHY модулей: C27 C28 R66 R67 R74 R75 R80 R81 R186 R189 R192 R195 R199 R202 R205 R207 X5

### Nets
+1.1V: C26.1 C28.1 C30.1 X4.42 X4.44 X4.46 X4.48 X4.50 X4.52 X4.54 X4.102 X4.104 X4.106 X4.108 X4.110 X4.112 X4.114 X5.42 X5.44 X5.46 X5.48 X5.50 X5.52 X5.54 X5.102 X5.104 X5.106 X5.108 X5.110 X5.112 X5.114 X6.42 X6.44 X6.46 X6.48 X6.50 X6.52 X6.54 X6.102 X6.104 X6.106 X6.108 X6.110 X6.112 X6.114
+3.3V: C25.1 C27.1 C29.1 R66.1 R67.1 R68.1 R69.1 R72.1 R73.1 R74.1 R75.1 R76.1 R77.1 R84.1 R85.1 R186.2 R189.2 R196.2 R199.2 R204.2 R206.2 R208.2 X4.41 X4.43 X4.45 X4.47 X4.49 X4.51 X4.53 X4.101 X4.103 X4.105 X4.107 X4.109 X4.111 X4.113 X5.41 X5.43 X5.45 X5.47 X5.49 X5.51 X5.53 X5.101 X5.103 X5.105 X5.107 X5.109 X5.111 X5.113 X6.41 X6.43 X6.45 X6.47 X6.49 X6.51 X6.53 X6.101 X6.103 X6.105 X6.107 X6.109 X6.111 X6.113
GND: C25.2 C26.2 C27.2 C28.2 C29.2 C30.2 R70.2 R71.2 R78.2 R79.2 R80.2 R81.2 R82.2 R83.2 R86.2 R87.2 R159.2 R187.2 R188.2 R190.2 R191.2 R192.2 R193.2 R194.2 R195.2 R197.2 R198.2 R200.2 R201.2 R202.2 R203.2 R205.2 R207.2 X4.5 X4.6 X4.23 X4.24 X4.27 X4.28 X4.33 X4.34 X4.36 X4.38 X4.55 X4.56 X4.65 X4.66 X4.83 X4.84 X4.87 X4.88 X4.93 X4.94 X4.96 X4.98 X4.115 X4.116 X4.121 X4.122 X4.123 X4.124 X4.125 X4.126 X4.127 X4.128 X5.5 X5.6 X5.23 X5.24 X5.27 X5.28 X5.33 X5.34 X5.36 X5.38 X5.55 X5.56 X5.65 X5.66 X5.83 X5.84 X5.87 X5.88 X5.93 X5.94 X5.96 X5.98 X5.115 X5.116 X5.121 X5.122 X5.123 X5.124 X5.125 X5.126 X5.127 X5.128 X6.5 X6.6 X6.23 X6.24 X6.27 X6.28 X6.33 X6.34 X6.36 X6.38 X6.55 X6.56 X6.65 X6.66 X6.83 X6.84 X6.87 X6.88 X6.93 X6.94 X6.96 X6.98 X6.115 X6.116 X6.121 X6.122 X6.123 X6.124 X6.125 X6.126 X6.127 X6.128
M_SGMII_L2DATI_0_N: X4.57
M_SGMII_L2DATI_0_P: X4.59
M_SGMII_L2DATI_1_N: X5.117
M_SGMII_L2DATI_1_P: X5.119
M_SGMII_L2DATI_2_N: X4.117
M_SGMII_L2DATI_2_P: X4.119
M_SGMII_L2DATI_3_N: X5.57
M_SGMII_L2DATI_3_P: X5.59
M_SGMII_L3DATI_0_N: R68.2 R70.1 X6.57
M_SGMII_L3DATI_0_P: R69.2 R71.1 X6.59
M_SGMII_L3DATI_2_N: R84.2 R86.1 X6.117
M_SGMII_L3DATI_2_P: R85.2 R87.1 X6.119
MDIO_2: X4.39 X4.99 X5.39 X5.99 X6.39 X6.99
P9_Addr_0: R159.1 X4.8
P9_Addr_1: R188.1 X4.10
P9_Addr_2: R191.1 X4.12
P9_Addr_3: R194.1 X4.14
P10_Addr_0: R199.1 X5.68
P10_Addr_1: R202.1 X5.70
P10_Addr_2: R205.1 X5.72
P10_Addr_3: R207.1 X5.74
P11_Addr_0: R197.1 X4.68
P11_Addr_1: R204.1 X4.70
P11_Addr_2: R198.1 X4.72
P11_Addr_3: R201.1 X4.74
P12_Addr_0: R186.1 X5.8
P12_Addr_1: R189.1 X5.10
P12_Addr_2: R192.1 X5.12
P12_Addr_3: R195.1 X5.14
P13_Addr_0: R187.1 X6.8
P13_Addr_1: R190.1 X6.10
P13_Addr_2: R196.1 X6.12
P13_Addr_3: R193.1 X6.14
P15_Addr_0: R200.1 X6.68
P15_Addr_1: R206.1 X6.70
P15_Addr_2: R208.1 X6.72
P15_Addr_3: R203.1 X6.74
PHY_9_RST#: X4.1
PHY_10_RST#: X5.61
PHY_11_RST#: X4.61
PHY_12_RST#: X5.1
PHY_13_RST#: X6.1
PHY_15_RST#: X6.61
SGMII_L2DATO_0_N: X4.58
SGMII_L2DATO_0_P: X4.60
SGMII_L2DATO_1_N: X5.118
SGMII_L2DATO_1_P: X5.120
SGMII_L2DATO_2_N: X4.118
SGMII_L2DATO_2_P: X4.120
SGMII_L2DATO_3_N: X5.58
SGMII_L2DATO_3_P: X5.60
SGMII_L3DATO_0_N: X6.58
SGMII_L3DATO_0_P: X6.60
SGMII_L3DATO_2_N: X6.118
SGMII_L3DATO_2_P: X6.120
X4_1_MDC_2: X4.40
X4_2_CON: R72.2 R78.1 X4.62
X4_2_COP: R73.2 R79.1 X4.64
X4_2_MDC_2: X4.100
X5_1_CON: R66.2 X5.2
X5_1_COP: R67.2 X5.4
X5_1_MDC_2: X5.40
X5_2_CON: R74.2 R80.1 X5.62
X5_2_COP: R75.2 R81.1 X5.64
X5_2_MDC_2: X5.100
X6_1_MDC_2: X6.40
X6_2_CON: R76.2 R82.1 X6.62
X6_2_COP: R77.2 R83.1 X6.64
X6_2_MDC_2: X6.100

Not connected (* = marked no-connect by the designer): X4 2 3 4 7 9 11 13 15 16 17 18 19 20 21 22 25 26 29 30 31 32 35 37 63 67 69 71 73 75 76 77 78 79 80 81 82 85 86 89 90 91 92 95 97; X5 3 7 9 11 13 15 16 17 18 19 20 21 22 25 26 29 30 31 32 35 37 63 67 69 71 73 75 76 77 78 79 80 81 82 85 86 89 90 91 92 95 97; X6 2 3 4 7 9 11 13 15 16 17 18 19 20 21 22 25 26 29 30 31 32 35 37 63 67 69 71 73 75 76 77 78 79 80 81 82 85 86 89 90 91 92 95 97

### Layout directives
differential pair: M_SGMII_L2DATI_0_N, M_SGMII_L2DATI_0_P, M_SGMII_L2DATI_1_N, M_SGMII_L2DATI_1_P, M_SGMII_L2DATI_2_N, M_SGMII_L2DATI_2_P, M_SGMII_L2DATI_3_N, M_SGMII_L2DATI_3_P, M_SGMII_L3DATI_0_N, M_SGMII_L3DATI_0_P, M_SGMII_L3DATI_2_N, M_SGMII_L3DATI_2_P, SGMII_L2DATO_0_N, SGMII_L2DATO_0_P, SGMII_L2DATO_1_N, SGMII_L2DATO_1_P, SGMII_L2DATO_2_N, SGMII_L2DATO_2_P, SGMII_L2DATO_3_N, SGMII_L2DATO_3_P, SGMII_L3DATO_0_N, SGMII_L3DATO_0_P, SGMII_L3DATO_2_N, SGMII_L3DATO_2_P

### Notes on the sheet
- MDIO bus 2, Address 0
- (near X4) SGMII Port 9
- MDIO bus 2, Address 3
- (near X5) SGMII Port 12
- MDIO bus 2, Address 4
- (near X6) SGMII Port 13
- (near X4) SGMII Port 11
- (near X5) SGMII Port 10
- (near X6) SGMII Port 15
- MDIO bus 2, Address 2
- MDIO bus 2, Address 1
- MDIO bus 2, Address 6

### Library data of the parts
C25-C30 = Cap_1206: GRM31CR60J107ME39L
R66 R67 R70 R71 R78-R83 R86 R87 R159 R186-R208 = Res_0402: CR0402-FX-2491GLF
R68 R69 R74 R75 R84 R85 = Res_0402: CR0402-FX-1102GLF
R72 R73 R76 R77 = Res_0402: CR0402-FX-6041GLF
X4-X6 = qsh-60-01-f-d-a: as X1 on sheet switch_1923KX028_v_2_sheet_2

## Sheet switch_1923KX028_v_2_sheet_4.SchDoc
size A3
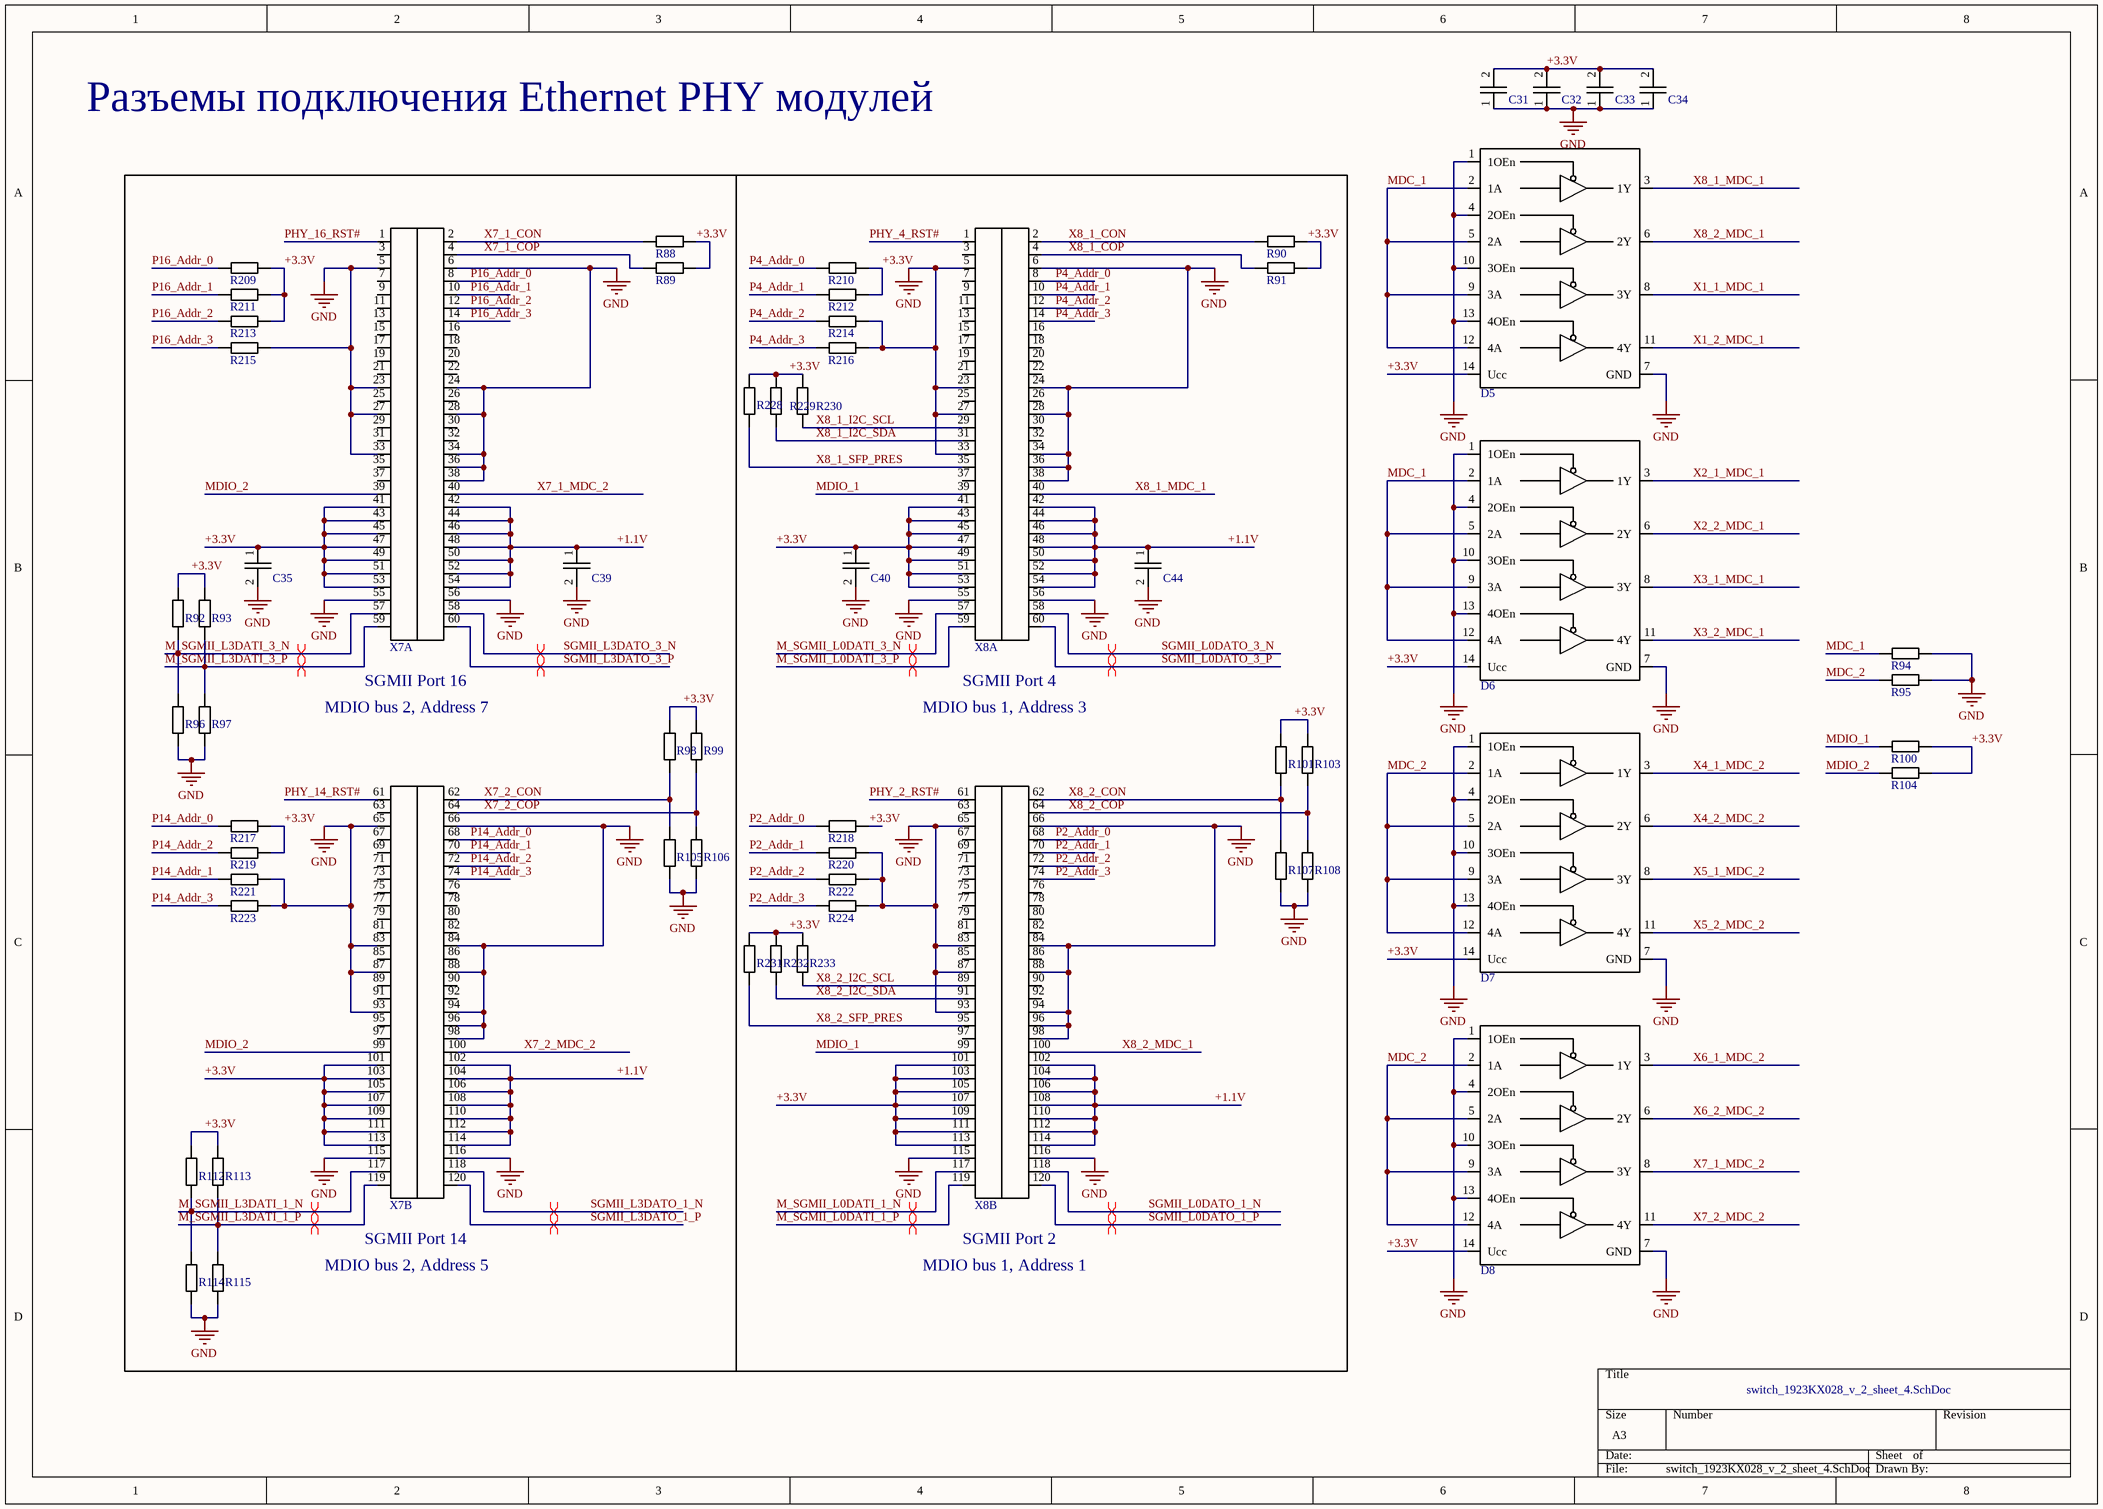
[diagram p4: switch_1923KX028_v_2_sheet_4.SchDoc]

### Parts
C31  100nF, 10V, X5R, 0402  [FOOTPRINT_0402]  (value not drawn)
C32  100nF, 10V, X5R, 0402  [FOOTPRINT_0402]  (value not drawn)
C33  100nF, 10V, X5R, 0402  [FOOTPRINT_0402]  (value not drawn)
C34  100nF, 10V, X5R, 0402  [FOOTPRINT_0402]  (value not drawn)
C35  100uF, X5R, 6.3В, 1206  [FOOTPRINT_1206]  (value not drawn)
C39  100uF, X5R, 6.3В, 1206  [FOOTPRINT_1206]  (value not drawn)
C40  100uF, X5R, 6.3В, 1206  [FOOTPRINT_1206]  (value not drawn)
C44  100uF, X5R, 6.3В, 1206  [FOOTPRINT_1206]  (value not drawn)
D5  SN74LVT125DR  [SOIC-14]  (value not drawn)
D6  SN74LVT125DR  [SOIC-14]  (value not drawn)
D7  SN74LVT125DR  [SOIC-14]  (value not drawn)
D8  SN74LVT125DR  [SOIC-14]  (value not drawn)
R88  2.49K, 1%, 0402  [FOOTPRINT_0402]  (value not drawn)
R89  2.49K, 1%, 0402  [FOOTPRINT_0402]  (value not drawn)
R90  2.49K, 1%, 0402  [FOOTPRINT_0402]  (value not drawn)
R91  2.49K, 1%, 0402  [FOOTPRINT_0402]  (value not drawn)
R92  11K, 1%, 0402  [FOOTPRINT_0402]  (value not drawn)
R93  11K, 1%, 0402  [FOOTPRINT_0402]  (value not drawn)
R94  11K, 1%, 0402  [FOOTPRINT_0402]  (value not drawn)
R95  11K, 1%, 0402  [FOOTPRINT_0402]  (value not drawn)
R96  2.49K, 1%, 0402  [FOOTPRINT_0402]  (value not drawn)
R97  2.49K, 1%, 0402  [FOOTPRINT_0402]  (value not drawn)
R98  11K, 1%, 0402  [FOOTPRINT_0402]  (value not drawn)
R99  11K, 1%, 0402  [FOOTPRINT_0402]  (value not drawn)
R100  1.82K, 1%, 0402  [FOOTPRINT_0402]  (value not drawn)
R101  11K, 1%, 0402  [FOOTPRINT_0402]  (value not drawn)
R103  11K, 1%, 0402  [FOOTPRINT_0402]  (value not drawn)
R104  1.82K, 1%, 0402  [FOOTPRINT_0402]  (value not drawn)
R105  2.49K, 1%, 0402  [FOOTPRINT_0402]  (value not drawn)
R106  2.49K, 1%, 0402  [FOOTPRINT_0402]  (value not drawn)
R107  2.49K, 1%, 0402  [FOOTPRINT_0402]  (value not drawn)
R108  2.49K, 1%, 0402  [FOOTPRINT_0402]  (value not drawn)
R112  11K, 1%, 0402  [FOOTPRINT_0402]  (value not drawn)
R113  11K, 1%, 0402  [FOOTPRINT_0402]  (value not drawn)
R114  2.49K, 1%, 0402  [FOOTPRINT_0402]  (value not drawn)
R115  2.49K, 1%, 0402  [FOOTPRINT_0402]  (value not drawn)
R209  2.49K, 1%, 0402  [FOOTPRINT_0402]  (value not drawn)
R210  2.49K, 1%, 0402  [FOOTPRINT_0402]  (value not drawn)
R211  2.49K, 1%, 0402  [FOOTPRINT_0402]  (value not drawn)
R212  2.49K, 1%, 0402  [FOOTPRINT_0402]  (value not drawn)
R213  2.49K, 1%, 0402  [FOOTPRINT_0402]  (value not drawn)
R214  2.49K, 1%, 0402  [FOOTPRINT_0402]  (value not drawn)
R215  2.49K, 1%, 0402  [FOOTPRINT_0402]  (value not drawn)
R216  2.49K, 1%, 0402  [FOOTPRINT_0402]  (value not drawn)
R217  2.49K, 1%, 0402  [FOOTPRINT_0402]  (value not drawn)
R218  2.49K, 1%, 0402  [FOOTPRINT_0402]  (value not drawn)
R219  2.49K, 1%, 0402  [FOOTPRINT_0402]  (value not drawn)
R220  2.49K, 1%, 0402  [FOOTPRINT_0402]  (value not drawn)
R221  2.49K, 1%, 0402  [FOOTPRINT_0402]  (value not drawn)
R222  2.49K, 1%, 0402  [FOOTPRINT_0402]  (value not drawn)
R223  2.49K, 1%, 0402  [FOOTPRINT_0402]  (value not drawn)
R224  2.49K, 1%, 0402  [FOOTPRINT_0402]  (value not drawn)
R228  11K, 1%, 0402  [FOOTPRINT_0402]  (value not drawn)
R229  11K, 1%, 0402  [FOOTPRINT_0402]  (value not drawn)
R230  11K, 1%, 0402  [FOOTPRINT_0402]  (value not drawn)
R231  11K, 1%, 0402  [FOOTPRINT_0402]  (value not drawn)
R232  11K, 1%, 0402  [FOOTPRINT_0402]  (value not drawn)
R233  11K, 1%, 0402  [FOOTPRINT_0402]  (value not drawn)
X7  qsh-60-01-f-d-a  [QSH-60-01-F-D-A]  (value not drawn)  (parts A,B of 2)
X8  qsh-60-01-f-d-a  [QSH-60-01-F-D-A]  (value not drawn)  (parts A,B of 2)

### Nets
+1.1V: C39.1 C44.1 X7.42 X7.44 X7.46 X7.48 X7.50 X7.52 X7.54 X7.102 X7.104 X7.106 X7.108 X7.110 X7.112 X7.114 X8.42 X8.44 X8.46 X8.48 X8.50 X8.52 X8.54 X8.102 X8.104 X8.106 X8.108 X8.110 X8.112 X8.114
+3.3V: C31.2 C32.2 C33.2 C34.2 C35.1 C40.1 D5.14(Ucc) D6.14(Ucc) D7.14(Ucc) D8.14(Ucc) R88.1 R89.1 R90.1 R91.1 R92.1 R93.1 R98.1 R99.1 R100.1 R101.1 R103.1 R104.1 R112.1 R113.1 R209.2 R210.2 R211.2 R212.2 R213.2 R217.2 R218.2 R219.2 R228.1 R229.1 R230.1 R231.1 R232.1 R233.1 X7.41 X7.43 X7.45 X7.47 X7.49 X7.51 X7.53 X7.101 X7.103 X7.105 X7.107 X7.109 X7.111 X7.113 X8.41 X8.43 X8.45 X8.47 X8.49 X8.51 X8.53 X8.101 X8.103 X8.105 X8.107 X8.109 X8.111 X8.113
GND: C31.1 C32.1 C33.1 C34.1 C35.2 C39.2 C40.2 C44.2 D5.1(1OEn) D5.4(2OEn) D5.7(GND) D5.10(3OEn) D5.13(4OEn) D6.1(1OEn) D6.4(2OEn) D6.7(GND) D6.10(3OEn) D6.13(4OEn) D7.1(1OEn) D7.4(2OEn) D7.7(GND) D7.10(3OEn) D7.13(4OEn) D8.1(1OEn) D8.4(2OEn) D8.7(GND) D8.10(3OEn) D8.13(4OEn) R94.1 R95.1 R96.2 R97.2 R105.2 R106.2 R107.2 R108.2 R114.2 R115.2 R214.2 R215.2 R216.2 R220.2 R221.2 R222.2 R223.2 R224.2 X7.5 X7.6 X7.23 X7.24 X7.27 X7.28 X7.33 X7.34 X7.36 X7.38 X7.55 X7.56 X7.65 X7.66 X7.83 X7.84 X7.87 X7.88 X7.93 X7.94 X7.96 X7.98 X7.115 X7.116 X7.121 X7.122 X7.123 X7.124 X7.125 X7.126 X7.127 X7.128 X8.5 X8.6 X8.23 X8.24 X8.27 X8.28 X8.33 X8.34 X8.36 X8.38 X8.55 X8.56 X8.65 X8.66 X8.83 X8.84 X8.87 X8.88 X8.93 X8.94 X8.96 X8.98 X8.115 X8.116 X8.121 X8.122 X8.123 X8.124 X8.125 X8.126 X8.127 X8.128
M_SGMII_L0DATI_1_N: X8.117
M_SGMII_L0DATI_1_P: X8.119
M_SGMII_L0DATI_3_N: X8.57
M_SGMII_L0DATI_3_P: X8.59
M_SGMII_L3DATI_1_N: R112.2 R114.1 X7.117
M_SGMII_L3DATI_1_P: R113.2 R115.1 X7.119
M_SGMII_L3DATI_3_N: R92.2 R96.1 X7.57
M_SGMII_L3DATI_3_P: R93.2 R97.1 X7.59
MDC_1: D5.2(1A) D5.5(2A) D5.9(3A) D5.12(4A) D6.2(1A) D6.5(2A) D6.9(3A) D6.12(4A) R94.2
MDC_2: D7.2(1A) D7.5(2A) D7.9(3A) D7.12(4A) D8.2(1A) D8.5(2A) D8.9(3A) D8.12(4A) R95.2
MDIO_1: R100.2 X8.39 X8.99
MDIO_2: R104.2 X7.39 X7.99
P2_Addr_0: R218.1 X8.68
P2_Addr_1: R220.1 X8.70
P2_Addr_2: R222.1 X8.72
P2_Addr_3: R224.1 X8.74
P4_Addr_0: R210.1 X8.8
P4_Addr_1: R212.1 X8.10
P4_Addr_2: R214.1 X8.12
P4_Addr_3: R216.1 X8.14
P14_Addr_0: R217.1 X7.68
P14_Addr_1: R221.1 X7.70
P14_Addr_2: R219.1 X7.72
P14_Addr_3: R223.1 X7.74
P16_Addr_0: R209.1 X7.8
P16_Addr_1: R211.1 X7.10
P16_Addr_2: R213.1 X7.12
P16_Addr_3: R215.1 X7.14
PHY_2_RST#: X8.61
PHY_4_RST#: X8.1
PHY_14_RST#: X7.61
PHY_16_RST#: X7.1
SGMII_L0DATO_1_N: X8.118
SGMII_L0DATO_1_P: X8.120
SGMII_L0DATO_3_N: X8.58
SGMII_L0DATO_3_P: X8.60
SGMII_L3DATO_1_N: X7.118
SGMII_L3DATO_1_P: X7.120
SGMII_L3DATO_3_N: X7.58
SGMII_L3DATO_3_P: X7.60
X1_1_MDC_1: D5.8(3Y)
X1_2_MDC_1: D5.11(4Y)
X2_1_MDC_1: D6.3(1Y)
X2_2_MDC_1: D6.6(2Y)
X3_1_MDC_1: D6.8(3Y)
X3_2_MDC_1: D6.11(4Y)
X4_1_MDC_2: D7.3(1Y)
X4_2_MDC_2: D7.6(2Y)
X5_1_MDC_2: D7.8(3Y)
X5_2_MDC_2: D7.11(4Y)
X6_1_MDC_2: D8.3(1Y)
X6_2_MDC_2: D8.6(2Y)
X7_1_CON: R88.2 X7.2
X7_1_COP: R89.2 X7.4
X7_1_MDC_2: D8.8(3Y) X7.40
X7_2_CON: R98.2 R105.1 X7.62
X7_2_COP: R99.2 R106.1 X7.64
X7_2_MDC_2: D8.11(4Y) X7.100
X8_1_CON: R90.2 X8.2
X8_1_COP: R91.2 X8.4
X8_1_I2C_SCL: R230.2 X8.29
X8_1_I2C_SDA: R229.2 X8.31
X8_1_MDC_1: D5.3(1Y) X8.40
X8_1_SFP_PRES: R228.2 X8.35
X8_2_CON: R101.2 R107.1 X8.62
X8_2_COP: R103.2 R108.1 X8.64
X8_2_I2C_SCL: R233.2 X8.89
X8_2_I2C_SDA: R232.2 X8.91
X8_2_MDC_1: D5.6(2Y) X8.100
X8_2_SFP_PRES: R231.2 X8.95

Not connected (* = marked no-connect by the designer): X7 3 7 9 11 13 15 16 17 18 19 20 21 22 25 26 29 30 31 32 35 37 63 67 69 71 73 75 76 77 78 79 80 81 82 85 86 89 90 91 92 95 97; X8 3 7 9 11 13 15 16 17 18 19 20 21 22 25 26 30 32 37 63 67 69 71 73 75 76 77 78 79 80 81 82 85 86 90 92 97

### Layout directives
differential pair: M_SGMII_L0DATI_1_N, M_SGMII_L0DATI_1_P, M_SGMII_L0DATI_3_N, M_SGMII_L0DATI_3_P, M_SGMII_L3DATI_1_N, M_SGMII_L3DATI_1_P, M_SGMII_L3DATI_3_N, M_SGMII_L3DATI_3_P, SGMII_L0DATO_1_N, SGMII_L0DATO_1_P, SGMII_L0DATO_3_N, SGMII_L0DATO_3_P, SGMII_L3DATO_1_N, SGMII_L3DATO_1_P, SGMII_L3DATO_3_N, SGMII_L3DATO_3_P

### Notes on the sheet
- Разъемы подключения Ethernet PHY модулей
- MDIO bus 2, Address 7
- (near X7) SGMII Port 16
- MDIO bus 1, Address 3
- (near X8) SGMII Port 4
- MDIO bus 2, Address 5
- (near X7) SGMII Port 14
- MDIO bus 1, Address 1
- (near X8) SGMII Port 2

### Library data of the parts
C31-C34 = Cap_0402: 0402ZD104KAT2A
C35 C39 C40 C44 = Cap_1206: GRM31CR60J107ME39L
D5-D8 = SN74LVT125DR: 4 buffers with 3-state outputs
R88-R91 R96 R97 R105-R108 R114 R115 R209-R224 = Res_0402: CR0402-FX-2491GLF
R92-R95 R98 R99 R101 R103 R112 R113 = Res_0402: CR0402-FX-1102GLF
R100 R104 = Res_0402: CR0402-FX-1821GLF
R228-R233 = Res: CR0402-FX-1102GLF
X7 X8 = qsh-60-01-f-d-a: as X1 on sheet switch_1923KX028_v_2_sheet_2

## Sheet switch_1923KX028_v_2_sheet_5.SchDoc
size A3; DocumentNumber: 10; SheetNumber: 10; SheetTotal: 10
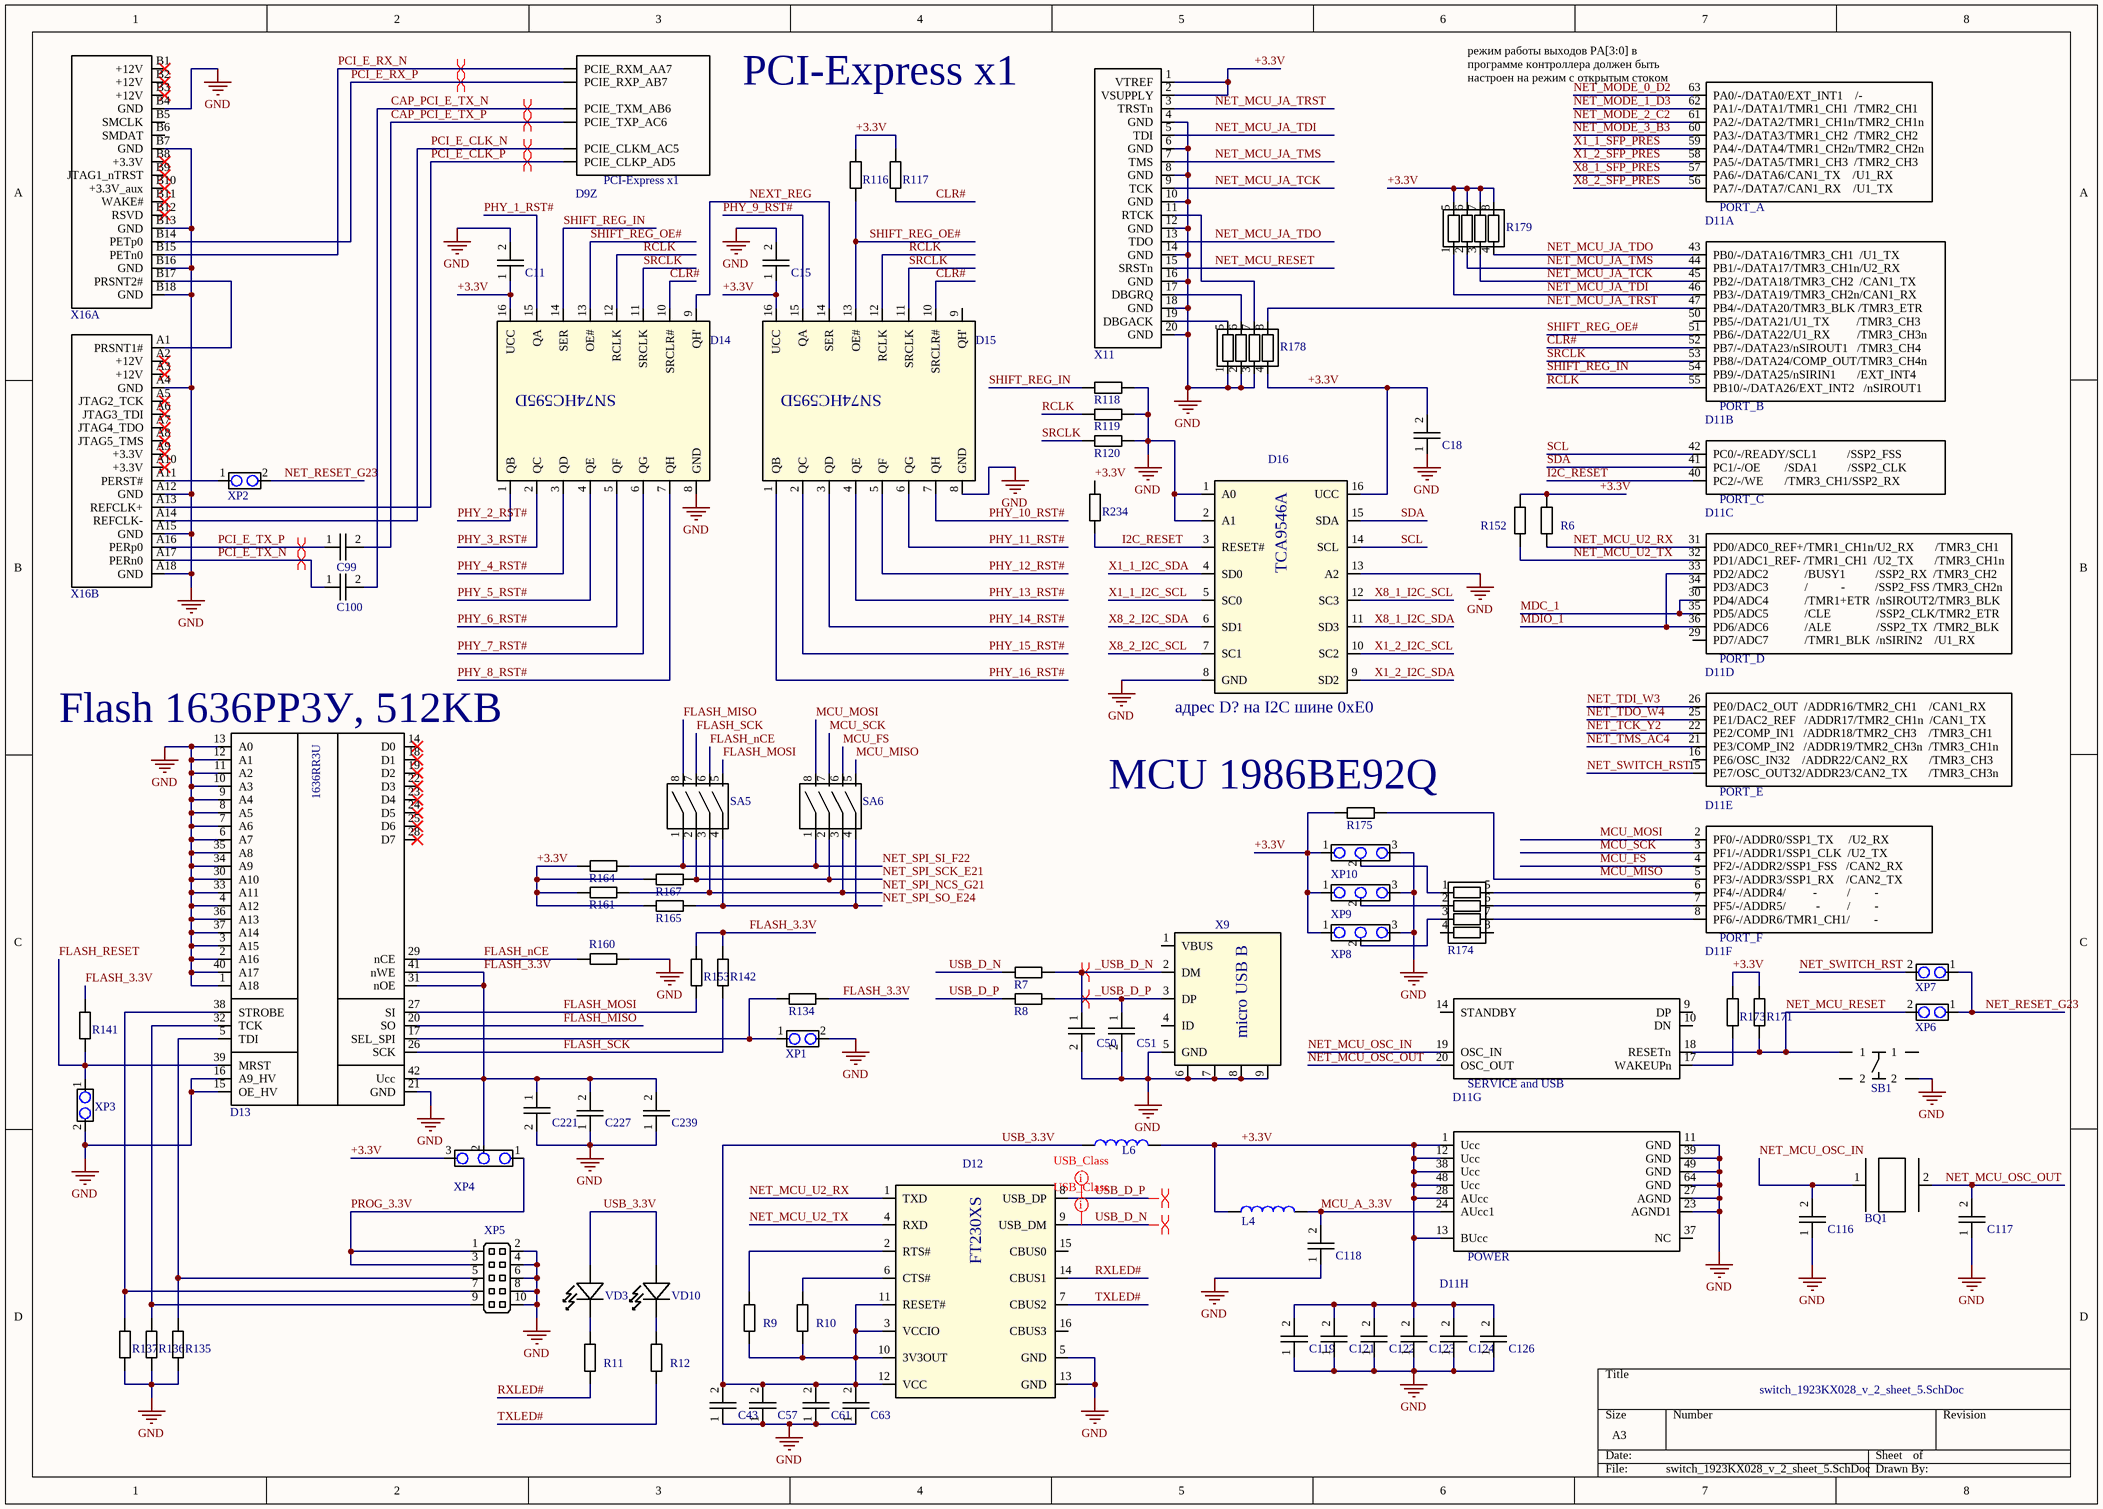
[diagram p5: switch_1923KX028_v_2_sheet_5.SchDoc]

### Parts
BQ1  8MHz, HS49SM  [HS49SM]  (value not drawn)
C11  100nF, 10V, X5R, 0402  [FOOTPRINT_0402]  (value not drawn)
C15  100nF, 10V, X5R, 0402  [FOOTPRINT_0402]  (value not drawn)
C18  100nF, 10V, X5R, 0402  [FOOTPRINT_0402]  (value not drawn)
C43  10 uF, 10%, 25V, X5R, 1206  [FOOTPRINT_1206]  (value not drawn)
C50  47 пФ, ±5%, NP0, 50В, 0603  [FOOTPRINT_0603]  (value not drawn)
C51  47 пФ, ±5%, NP0, 50В, 0603  [FOOTPRINT_0603]  (value not drawn)
C57  100nF, 10V, X5R, 0402  [FOOTPRINT_0402]  (value not drawn)
C61  100nF, 10V, X5R, 0402  [FOOTPRINT_0402]  (value not drawn)
C63  100nF, 10V, X5R, 0402  [FOOTPRINT_0402]  (value not drawn)
C99  100nF, 10V, X5R, 0402  [FOOTPRINT_0402]  (value not drawn)
C100  100nF, 10V, X5R, 0402  [FOOTPRINT_0402]  (value not drawn)
C116  18pF, 50V, C0G, 0402  [FOOTPRINT_0402]  (value not drawn)
C117  18pF, 50V, C0G, 0402  [FOOTPRINT_0402]  (value not drawn)
C118  100nF, 10V, X5R, 0402  [FOOTPRINT_0402]  (value not drawn)
C119  100nF, 10V, X5R, 0402  [FOOTPRINT_0402]  (value not drawn)
C121  100uF, X5R, 6.3В, 1206  [FOOTPRINT_1206]  (value not drawn)
C122  100nF, 10V, X5R, 0402  [FOOTPRINT_0402]  (value not drawn)
C123  100nF, 10V, X5R, 0402  [FOOTPRINT_0402]  (value not drawn)
C124  100nF, 10V, X5R, 0402  [FOOTPRINT_0402]  (value not drawn)
C126  100nF, 10V, X5R, 0402  [FOOTPRINT_0402]  (value not drawn)
C221  1.0uF, 10V, X5R, 0402  [FOOTPRINT_0402]  (value not drawn)
C227  100nF, 10V, X5R, 0402  [FOOTPRINT_0402]  (value not drawn)
C239  100uF, X5R, 6.3В, 1206  [FOOTPRINT_1206]  (value not drawn)
D9  1923KX028  [FOOTPRINT_MK8303.576-1]  (value not drawn)  (part Z of 27)
D11  1986BE92Q  [LQFP64]  (value not drawn)  (parts A,B,C,D,E,F,G,H of 8)
D12  FT230XS  [SSOP-16]  (value not drawn)
D13  1636RR3U  [FOOTPRINT_H14.42-1B]  (value not drawn)
D14  SN74HC595  [SOIC-16]  (value not drawn)
D15  SN74HC595  [SOIC-16]  (value not drawn)
D16  TCA9546ADR  [SOIC-16]  (value not drawn)
L4  0805  [FOOTPRINT_0805]  (value not drawn)
L6  0805  [FOOTPRINT_0805]  (value not drawn)
R6  11K, 1%, 0402  [FOOTPRINT_0402]  (value not drawn)
R7  24, 1%, 0402  [FOOTPRINT_0402]  (value not drawn)
R8  24, 1%, 0402  [FOOTPRINT_0402]  (value not drawn)
R9  11K, 1%, 0402  [FOOTPRINT_0402]  (value not drawn)
R10  11K, 1%, 0402  [FOOTPRINT_0402]  (value not drawn)
R11  280 1% 0402  [FOOTPRINT_0402]  (value not drawn)
R12  280 1% 0402  [FOOTPRINT_0402]  (value not drawn)
R116  11K, 1%, 0402  [FOOTPRINT_0402]  (value not drawn)
R117  11K, 1%, 0402  [FOOTPRINT_0402]  (value not drawn)
R118  11K, 1%, 0402  [FOOTPRINT_0402]  (value not drawn)
R119  11K, 1%, 0402  [FOOTPRINT_0402]  (value not drawn)
R120  11K, 1%, 0402  [FOOTPRINT_0402]  (value not drawn)
R134  11K, 1%, 0402  [FOOTPRINT_0402]  (value not drawn)
R135  11K, 1%, 0402  [FOOTPRINT_0402]  (value not drawn)
R136  11K, 1%, 0402  [FOOTPRINT_0402]  (value not drawn)
R137  11K, 1%, 0402  [FOOTPRINT_0402]  (value not drawn)
R141  11K, 1%, 0402  [FOOTPRINT_0402]  (value not drawn)
R142  11K, 1%, 0402  [FOOTPRINT_0402]  (value not drawn)
R152  11K, 1%, 0402  [FOOTPRINT_0402]  (value not drawn)
R153  11K, 1%, 0402  [FOOTPRINT_0402]  (value not drawn)
R160  2K, 1%, 0603  [FOOTPRINT_0603]  (value not drawn)
R161  11K, 1%, 0402  [FOOTPRINT_0402]  (value not drawn)
R164  11K, 1%, 0402  [FOOTPRINT_0402]  (value not drawn)
R165  11K, 1%, 0402  [FOOTPRINT_0402]  (value not drawn)
R167  11K, 1%, 0402  [FOOTPRINT_0402]  (value not drawn)
R171  11K, 1%, 0402  [FOOTPRINT_0402]  (value not drawn)
R173  11K, 1%, 0402  [FOOTPRINT_0402]  (value not drawn)
R174  4 x 10K, 5%, 0804  [FOOTPRINT_0804_RES_ARRAY]  (value not drawn)
R175  11K, 1%, 0402  [FOOTPRINT_0402]  (value not drawn)
R178  4 x 10K, 5%, 0804  [FOOTPRINT_0804_RES_ARRAY]  (value not drawn)
R179  4 x 10K, 5%, 0804  [FOOTPRINT_0804_RES_ARRAY]  (value not drawn)
R234  11K, 1%, 0402  [FOOTPRINT_0402]  (value not drawn)
SA5  DMHA-04G-G  [FOOTPRINT_DMHA-04G-G]  (value not drawn)
SA6  DMHA-04G-G  [FOOTPRINT_DMHA-04G-G]  (value not drawn)
SB1  7914G-1-000 Е  [7914G_1_000_E]  (value not drawn)
VD3  KP-2012SYCK  [FOOTPRINT_SMD_LED_2.0x1.25mm]  (value not drawn)
VD10  KP-2012SYCK  [FOOTPRINT_SMD_LED_2.0x1.25mm]  (value not drawn)
X9  10104110-0001LF  [10104110-0001LF]  (value not drawn)
X11  IDC-20MS  [IDC-20MS]  (value not drawn)
X16  PCI_E x1  [PCI_E_x1]  (value not drawn)  (parts A,B of 2)
XP1  PLS-2  [PLS-2]  (value not drawn)
XP2  PLS-2  [PLS-2]  (value not drawn)
XP3  PLS-2  [PLS-2]  (value not drawn)
XP4  PLS-3  [PLS-3]  (value not drawn)
XP5  PLD-10  [FOOTPRINT_PLD10]  (value not drawn)
XP6  PLS-2  [PLS-2]  (value not drawn)
XP7  PLS-2  [PLS-2]  (value not drawn)
XP8  PLS-3  [PLS-3]  (value not drawn)
XP9  PLS-3  [PLS-3]  (value not drawn)
XP10  PLS-3  [PLS-3]  (value not drawn)

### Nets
+3.3V: C11.1 C15.1 C18.2 C119.2 C121.2 C122.2 C123.2 C124.2 C126.2 D11.1(Ucc) D11.12(Ucc) D11.13(BUcc) D11.28(AUcc) D11.38(Ucc) D11.48(Ucc) D14.16(UCC) D15.16(UCC) D16.16(UCC) L4.1 L6.2 R6.1 R116.2 R117.2 R152.1 R161.2 R164.2 R165.2 R167.2 R171.1 R173.1 R175.1 R178.4 R179.5 R179.6 R179.7 R179.8 R234.1 X11.1(VTREF) X11.2(VSUPPLY) XP4.3 XP8.1 XP9.1 XP10.1
GND: C11.2 C15.2 C18.1 C43.1 C50.2 C51.2 C57.1 C61.1 C63.1 C116.1 C117.1 C118.1 C119.1 C121.1 C122.1 C123.1 C124.1 C126.1 C221.2 C227.1 C239.1 D11.11(GND) D11.23(AGND1) D11.27(AGND) D11.39(GND) D11.49(GND) D11.64(GND) D12.5(GND) D12.13(GND) D13.1(A18) D13.2(A16) D13.3(A15) D13.4(A12) D13.6(A7) D13.7(A6) D13.8(A5) D13.9(A4) D13.10(A3) D13.11(A2) D13.12(A1) D13.13(A0) D13.15(OE_HV) D13.16(A9_HV) D13.21(GND) D13.30(A10) D13.33(A11) D13.34(A9) D13.35(A8) D13.36(A13) D13.37(A14) D13.40(A17) D14.8(GND) D15.8(GND) D16.1(A0) D16.2(A1) D16.8(GND) D16.13(A2) R118.1 R119.1 R120.1 R135.2 R136.2 R137.2 R160.1 R178.1 R178.2 R178.3 SB1.3(2) X9.5(GND) X9.6(GND) X9.7(GND) X9.8(GND) X9.9(GND) X11.4(GND) X11.6(GND) X11.8(GND) X11.10(GND) X11.12(GND) X11.14(GND) X11.16(GND) X11.18(GND) X11.20(GND) X16.A4(GND) X16.A12(GND) X16.A15(GND) X16.A18(GND) X16.B4(GND) X16.B7(GND) X16.B13(GND) X16.B16(GND) X16.B18(GND) XP1.2 XP3.2 XP5.2 XP5.4 XP5.6 XP5.8 XP5.10 XP8.3 XP9.3 XP10.3
_USB_D_N: C50.1 R7.2 X9.2(DM)
_USB_D_P: C51.1 R8.2 X9.3(DP)
CAP_PCI_E_TX_N: C100.2 D9.AB6(PCIE_TXM_AB6)
CAP_PCI_E_TX_P: C99.2 D9.AC6(PCIE_TXP_AC6)
CLR#: D11.52(PB7/-/DATA23/nSIROUT1___/TMR3_CH4) D14.10(SRCLR#) D15.10(SRCLR#) R117.1
FLASH_3.3V: C221.1 C227.2 C239.2 D13.31(nOE) D13.41(nWE) D13.42(Ucc) R134.2 R141.1 R142.1 R153.1 XP4.2
FLASH_MISO: D13.20(SO) SA5.8
FLASH_MOSI: D13.27(SI) R153.2 SA5.5
FLASH_nCE: D13.29(nCE) R160.2 SA5.6
FLASH_RESET: D13.39(MRST) R141.2 XP3.1
FLASH_SCK: D13.26(SCK) R142.2 SA5.7
I2C_RESET: D11.40(PC2/-/WE_______/TMR3_CH1/SSP2_RX) D16.3(RESET#) R234.2
MCU_A_3.3V: C118.2 D11.24(AUcc1) L4.2
MCU_FS: D11.4(PF2/-/ADDR2/SSP1_FSS___/CAN2_RX) SA6.6
MCU_MISO: D11.5(PF3/-/ADDR3/SSP1_RX____/CAN2_TX) R175.2 SA6.5
MCU_MOSI: D11.2(PF0/-/ADDR0/SSP1_TX_____/U2_RX) SA6.8
MCU_SCK: D11.3(PF1/-/ADDR1/SSP1_CLK__/U2_TX) SA6.7
MDC_1: D11.30(PD4/ADC4____________/TMR1+ETR__/nSIROUT2/TMR3_BLK) D11.35(PD5/ADC5____________/CLE_______________/SSP2_CLK/TMR2_ETR)
MDIO_1: D11.33(PD2/ADC2____________/BUSY1__________/SSP2_RX__/TMR3_CH2) D11.36(PD6/ADC6____________/ALE_______________/SSP2_TX__/TMR2_BLK)
NET_MCU_JA_TCK: D11.45(PB2/-/DATA18/TMR3_CH2__/CAN1_TX) R179.3 X11.9(TCK)
NET_MCU_JA_TDI: D11.46(PB3/-/DATA19/TMR3_CH2n/CAN1_RX) R179.1 X11.5(TDI)
NET_MCU_JA_TDO: D11.43(PB0/-/DATA16/TMR3_CH1__/U1_TX) R179.4 X11.13(TDO)
NET_MCU_JA_TMS: D11.44(PB1/-/DATA17/TMR3_CH1n/U2_RX) R179.2 X11.7(TMS)
NET_MCU_JA_TRST: D11.47(PB4/-/DATA20/TMR3_BLK_/TMR3_ETR) R178.8 X11.3(TRSTn)
NET_MCU_OSC_IN: BQ1.1 C116.2 D11.19(OSC_IN)
NET_MCU_OSC_OUT: BQ1.2 C117.2 D11.20(OSC_OUT)
NET_MCU_RESET: D11.18(RESETn) R171.2 SB1.1 X11.15(SRSTn) XP6.2
NET_MCU_U2_RX: D11.31(PD0/ADC0_REF+/TMR1_CH1n/U2_RX_______/TMR3_CH1) D12.1(TXD) R6.2
NET_MCU_U2_TX: D11.32(PD1/ADC1_REF-_/TMR1_CH1__/U2_TX_______/TMR3_CH1n) D12.4(RXD) R152.2
NET_MODE_0_D2: D11.63(PA0/-/DATA0/EXT_INT1____/-)
NET_MODE_1_D3: D11.62(PA1/-/DATA1/TMR1_CH1__/TMR2_CH1)
NET_MODE_2_C2: D11.61(PA2/-/DATA2/TMR1_CH1n/TMR2_CH1n)
NET_MODE_3_B3: D11.60(PA3/-/DATA3/TMR1_CH2__/TMR2_CH2)
NET_RESET_G23: XP2.2 XP6.1 XP7.1
NET_SPI_NCS_G21: R161.1 SA5.3 SA6.3
NET_SPI_SCK_E21: R167.1 SA5.2 SA6.2
NET_SPI_SI_F22: R164.1 SA5.1 SA6.1
NET_SPI_SO_E24: R165.1 SA5.4 SA6.4
NET_SWITCH_RST: D11.15(PE7/OSC_OUT32/ADDR23/CAN2_TX_______/TMR3_CH3n) XP7.2
NET_TCK_Y2: D11.22(PE2/COMP_IN1___/ADDR18/TMR2_CH3____/TMR3_CH1)
NET_TDI_W3: D11.26(PE0/DAC2_OUT__/ADDR16/TMR2_CH1____/CAN1_RX)
NET_TDO_W4: D11.25(PE1/DAC2_REF___/ADDR17/TMR2_CH1n__/CAN1_TX)
NET_TMS_AC4: D11.21(PE3/COMP_IN2___/ADDR19/TMR2_CH3n__/TMR3_CH1n)
NEXT_REG: D14.9(QH') D15.14(SER)
PCI_E_CLK_N: D9.AC5(PCIE_CLKM_AC5) X16.A14(REFCLK-)
PCI_E_CLK_P: D9.AD5(PCIE_CLKP_AD5) X16.A13(REFCLK+)
PCI_E_RX_N: D9.AA7(PCIE_RXM_AA7) X16.B15(PETn0)
PCI_E_RX_P: D9.AB7(PCIE_RXP_AB7) X16.B14(PETp0)
PCI_E_TX_N: C100.1 X16.A17(PERn0)
PCI_E_TX_P: C99.1 X16.A16(PERp0)
PHY_1_RST#: D14.15(QA)
PHY_2_RST#: D14.1(QB)
PHY_3_RST#: D14.2(QC)
PHY_4_RST#: D14.3(QD)
PHY_5_RST#: D14.4(QE)
PHY_6_RST#: D14.5(QF)
PHY_7_RST#: D14.6(QG)
PHY_8_RST#: D14.7(QH)
PHY_9_RST#: D15.15(QA)
PHY_10_RST#: D15.7(QH)
PHY_11_RST#: D15.6(QG)
PHY_12_RST#: D15.5(QF)
PHY_13_RST#: D15.4(QE)
PHY_14_RST#: D15.3(QD)
PHY_15_RST#: D15.2(QC)
PHY_16_RST#: D15.1(QB)
PROG_3.3V: XP4.1 XP5.1 XP5.3
RCLK: D11.55(PB10/-/DATA26/EXT_INT2___/nSIROUT1) D14.12(RCLK) D15.12(RCLK) R119.2
RXLED#: D12.14(CBUS1) R11.2
SCL: D11.42(PC0/-/READY/SCL1__________/SSP2_FSS) D16.14(SCL)
SDA: D11.41(PC1/-/OE________/SDA1__________/SSP2_CLK) D16.15(SDA)
SHIFT_REG_IN: D11.54(PB9/-/DATA25/nSIRIN1_______/EXT_INT4) D14.14(SER) R118.2
SHIFT_REG_OE#: D11.51(PB6/-/DATA22/U1_RX_________/TMR3_CH3n) D14.13(OE#) D15.13(OE#) R116.1
SRCLK: D11.53(PB8/-/DATA24/COMP_OUT/TMR3_CH4n) D14.11(SRCLK) D15.11(SRCLK) R120.2
TXLED#: D12.7(CBUS2) R12.2
USB_3.3V: C43.2 C57.2 C61.2 C63.2 D12.3(VCCIO) D12.10(3V3OUT) D12.11(RESET#) D12.12(VCC) L6.1 R9.2 R10.2 VD3.1(A) VD10.1(A)
USB_D_N: D12.9(USB_DM) R7.1
USB_D_P: D12.8(USB_DP) R8.1
X1_1_I2C_SCL: D16.5(SC0)
X1_1_I2C_SDA: D16.4(SD0)
X1_1_SFP_PRES: D11.59(PA4/-/DATA4/TMR1_CH2n/TMR2_CH2n)
X1_2_I2C_SCL: D16.10(SC2)
X1_2_I2C_SDA: D16.9(SD2)
X1_2_SFP_PRES: D11.58(PA5/-/DATA5/TMR1_CH3__/TMR2_CH3)
X8_1_I2C_SCL: D16.12(SC3)
X8_1_I2C_SDA: D16.11(SD3)
X8_1_SFP_PRES: D11.57(PA6/-/DATA6/CAN1_TX____/U1_RX)
X8_2_I2C_SCL: D16.7(SC1)
X8_2_I2C_SDA: D16.6(SD1)
X8_2_SFP_PRES: D11.56(PA7/-/DATA7/CAN1_RX____/U1_TX)
NetD11_6: D11.6(PF4/-/ADDR4/_________-__________/________-) R174.5
NetD11_7: D11.7(PF5/-/ADDR5/__________-_________/________-) R174.6
NetD11_8: D11.8(PF6/-/ADDR6/TMR1_CH1/________-) R174.7
NetD11_17: D11.17(WAKEUPn) R173.2
NetD12_2: D12.2(RTS#) R9.1
NetD12_6: D12.6(CTS#) R10.1
NetD13_5: D13.5(TDI) R135.1 XP5.5
NetD13_17: D13.17(SEL_SPI) R134.1 XP1.1
NetD13_32: D13.32(TCK) R136.1 XP5.9
NetD13_38: D13.38(STROBE) R137.1 XP5.7
NetR11_1: R11.1 VD3.2(C)
NetR12_1: R12.1 VD10.2(C)
NetR174_1: R174.1 XP10.2
NetR174_2: R174.2 XP9.2
NetR174_3: R174.3 XP8.2
NetR178_5: R178.5 X11.19(DBGACK)
NetR178_6: R178.6 X11.17(DBGRQ)
NetR178_7: R178.7 X11.11(RTCK)
NetX16_A1: X16.A1(PRSNT1#) X16.B17(PRSNT2#)
NetX16_A11: X16.A11(PERST#) XP2.1

Not connected (* = marked no-connect by the designer): D11 9(DP) 10(DN) 14(STANDBY) 16(PE6/OSC_IN32____/ADDR22/CAN2_RX_______/TMR3_CH3) 29(PD7/ADC7____________/TMR1_BLK__/nSIRIN2____/U1_RX) 34(PD3/ADC3____________/___________-__________/SSP2_FSS_/TMR3_CH2n) 37(NC) 50(PB5/-/DATA21/U1_TX_________/TMR3_CH3); D12 15(CBUS0) 16(CBUS3); D13 14(D0)* 18(D1)* 19(D2)* 22(D3)* 23(D4)* 24(D5)* 25(D6)* 28(D7)*; D15 9(QH'); R174 4 8; SB1 2 4(1); X9 1(VBUS) 4(ID); X16 A2(+12V)* A3(+12V)* A5(JTAG2_TCK)* A6(JTAG3_TDI)* A7(JTAG4_TDO)* A8(JTAG5_TMS)* A9(+3.3V)* A10(+3.3V)* B1(+12V)* B2(+12V)* B3(+12V)* B5(SMCLK) B6(SMDAT) B8(+3.3V)* B9(JTAG1_nTRST)* B10(+3.3V_aux)* B11(WAKE#)* B12(RSVD)*

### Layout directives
differential pair: _USB_D_N, _USB_D_P, CAP_PCI_E_TX_N, CAP_PCI_E_TX_P, PCI_E_CLK_N, PCI_E_CLK_P, PCI_E_RX_N, PCI_E_RX_P, PCI_E_TX_N, PCI_E_TX_P, USB_D_N, USB_D_P
net class Undefined; rule Differential Pairs Routing [Pref Gap = 0.254mm    Min Gap  = 0.125mm    Max Gap  = 0.3mmPref Width = 0.381mm    Min Width  = 0.125mm    Max Width  = 0.381mm]: USB_D_N, USB_D_P

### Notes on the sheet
- PCI-Express x1
- (near D11) режим работы выходов PA[3:0] в программе контроллера должен быть настроен на режим с открытым стоком
- (near D16) адрес D? на I2C шине 0xE0
- (near D13) Flash 1636РР3У, 512KB
- (near R175) MCU 1986BE92Q

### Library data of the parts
BQ1 = Quartz_Crystal_HC49_S: GEYER 12.87823
C11 C15 C18 C57 C61 C63 C99 C100 C118 C119 C122-C124 C126 C227 = Cap_0402: 0402ZD104KAT2A
C43 = Cap_1206: 12063D106KAT2A
C50 C51 = Cap: CGA3E2C0G1H470J080AA
C116 C117 = Cap_0402: 04025A180JAT2A
C121 C239 = Cap_1210: GRM31CR60J107ME39L
C221 = Cap_0402: 0402ZD105KAT2A
D9 = 1923KX028: Milandr, 16 ports Ethernet Switch 1000/100/10
D11 = MCU_1986BE92Q: Milandr, 32-bit MCU
D12 = FT230XS: USB to BASIC UART IC
D13 = 1636RR3: Flash 512KB, H14.42-1B, Milandr
D14 D15 = SN74HC595: 8-Bit Shift Registers With 3-State Output Registers
D16 = TCA9546A: Low Voltage 4-Channel I2C and SMBus Switch with Reset Function
L4 L6 = L_0805: BLM21PG331SN1
R6 R9 R10 R116-R120 R134-R137 R141 R142 R152 R153 R161 R164 R165 R167 R171 R173 R175 R234 = Res: CR0402-FX-1102GLF
R7 R8 = Res: RC0402FR-0724RL
R11 R12 = Res: CR0402-FX-2800GLF
R160 = Res: CR0603-FX-2001ELF
R174 R178 R179 = RES_ARRAY_YC124_YAGEO: YC124-JR-0710KL
SA5 SA6 = dip_switch: dip_switch (4 poles)
SB1 = KEY_BOURNS_7914G_1_000_E: smd key, 5 x 5 mm, h = 1.65 mm
VD3 VD10 = Vd_led: as VD1 on sheet switch_1923KX028_v_2_sheet_1
X9 = 10104110-0001LF: MICRO USB B TYPE RECEPTACLE
X16 = PCI_Express_x1: PCI-Express x1
XP5 = PLD-10: PLD-10, step 2.54 mm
